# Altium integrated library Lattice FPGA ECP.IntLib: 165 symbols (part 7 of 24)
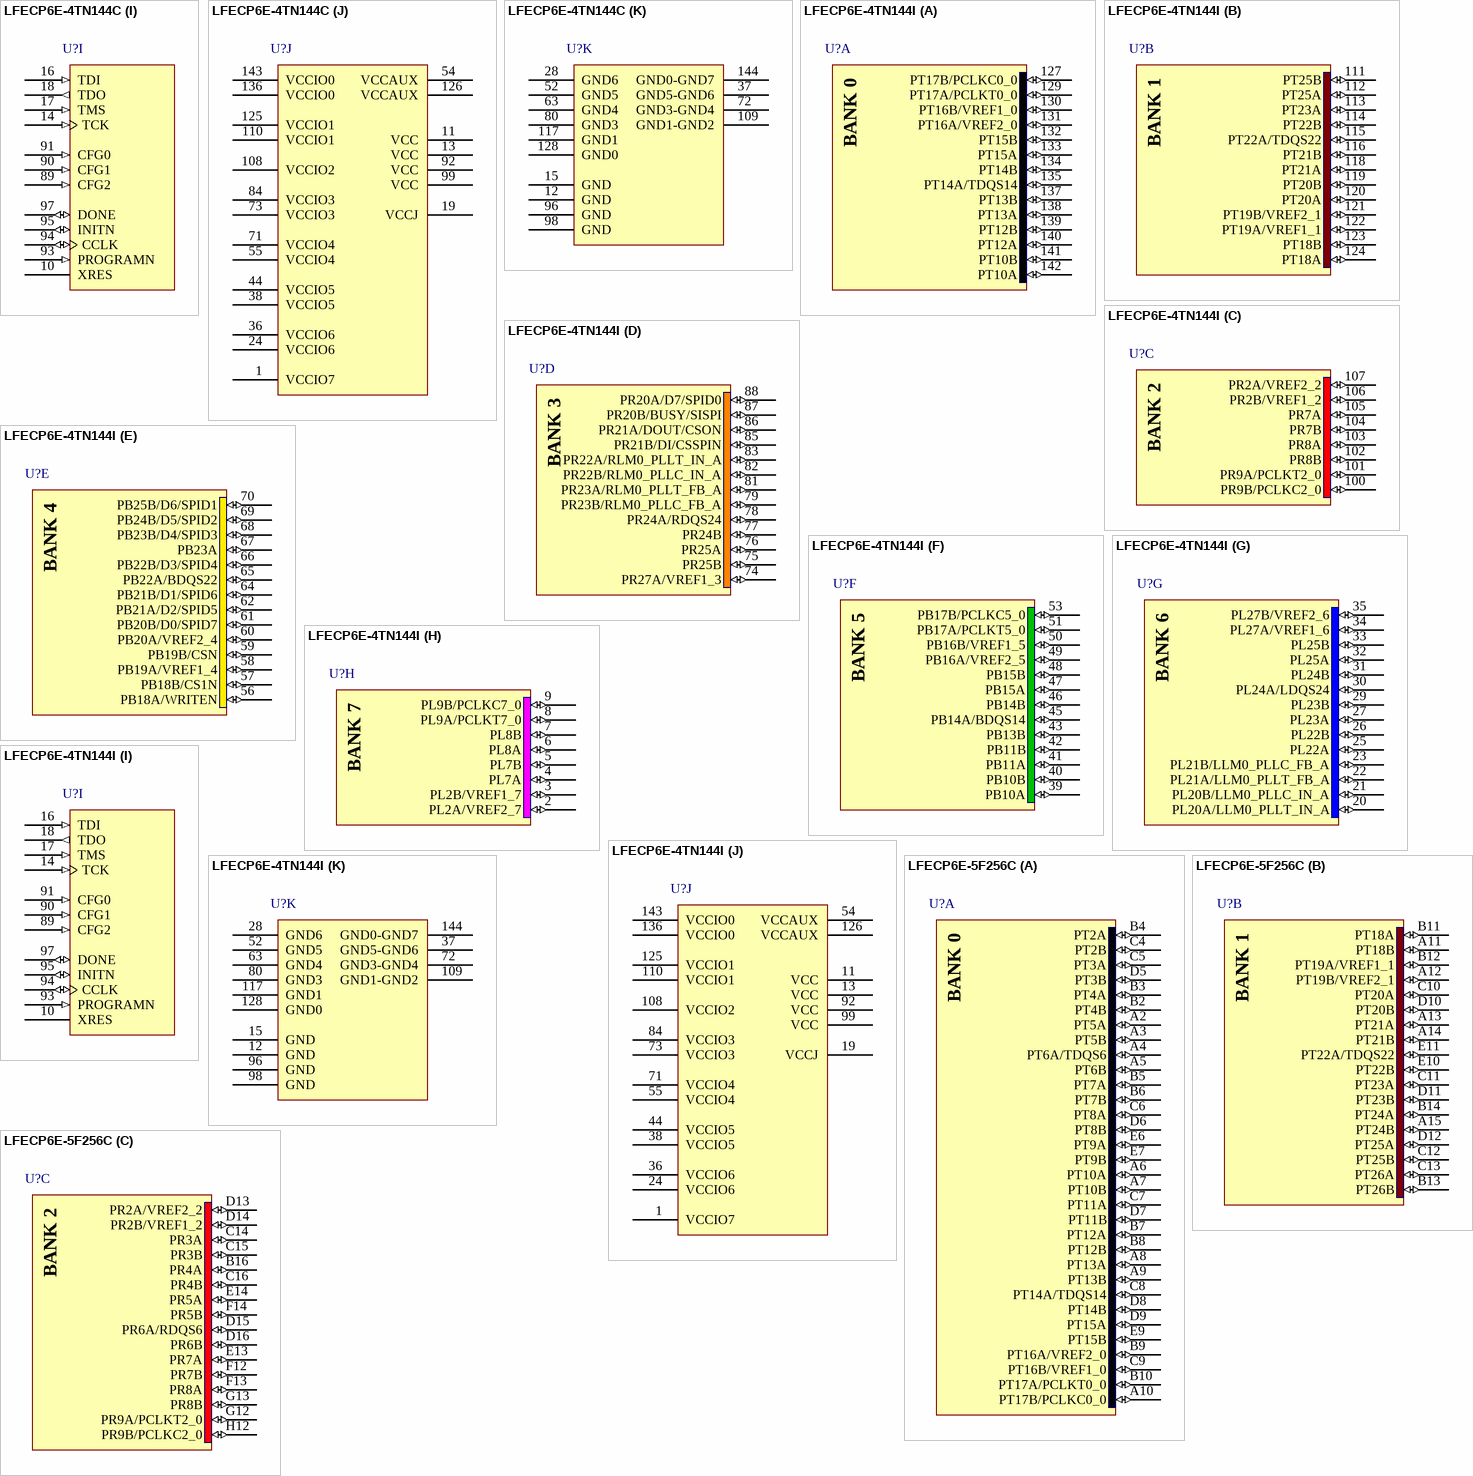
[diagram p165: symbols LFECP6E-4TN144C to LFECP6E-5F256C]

## LFECP6E-4TN144I
designator U?
ECP 1.2V FPGA, 97 I/Os, 2 PLLs, 6.1K LUTs, 4 sysDSP Blocks, 16 18x18 Multipliers, 144-Pin TQFP, Pb-Free, Speed Grade 4, Industrial Temperature Grade; Note: Pins 37, 72, 109 and 144 are double bonded.
footprint TQFP144_N (Thin QFP, 144-Leads, Body 20x20mm, Pitch 0.5mm, IPC Medium Density)
footprint TQFP144_L (Thin QFP, 144-Leads, Body 20x20mm, Pitch 0.5mm, IPC High Density)
footprint TQFP144_M (Thin QFP, 144-Leads, Body 20x20mm, Pitch 0.5mm, IPC Low Density)
3D model ECP6E-TQFP-144 (144-Pin Thin Quad Flat Pack (TQFP144))
part A pins: 127 PT17B/PCLKC0_0 (io), 129 PT17A/PCLKT0_0 (io), 130 PT16B/VREF1_0 (io), 131 PT16A/VREF2_0 (io), 132 PT15B (io), 133 PT15A (io), 134 PT14B (io), 135 PT14A/TDQS14 (io), 137 PT13B (io), 138 PT13A (io), 139 PT12B (io), 140 PT12A (io), 141 PT10B (io), 142 PT10A (io)
part B pins: 111 PT25B (io), 112 PT25A (io), 113 PT23A (io), 114 PT22B (io), 115 PT22A/TDQS22 (io), 116 PT21B (io), 118 PT21A (io), 119 PT20B (io), 120 PT20A (io), 121 PT19B/VREF2_1 (io), 122 PT19A/VREF1_1 (io), 123 PT18B (io), 124 PT18A (io)
part C pins: 100 PR9B/PCLKC2_0 (io), 101 PR9A/PCLKT2_0 (io), 102 PR8B (io), 103 PR8A (io), 104 PR7B (io), 105 PR7A (io), 106 PR2B/VREF1_2 (io), 107 PR2A/VREF2_2 (io)
part D pins: 74 PR27A/VREF1_3 (io), 75 PR25B (io), 76 PR25A (io), 77 PR24B (io), 78 PR24A/RDQS24 (io), 79 PR23B/RLM0_PLLC_FB_A (io), 81 PR23A/RLM0_PLLT_FB_A (io), 82 PR22B/RLM0_PLLC_IN_A (io), 83 PR22A/RLM0_PLLT_IN_A (io), 85 PR21B/DI/CSSPIN (io), 86 PR21A/DOUT/CSON (io), 87 PR20B/BUSY/SISPI (io), 88 PR20A/D7/SPID0 (io)
part E pins: 56 PB18A/WRITEN (io), 57 PB18B/CS1N (io), 58 PB19A/VREF1_4 (io), 59 PB19B/CSN (io), 60 PB20A/VREF2_4 (io), 61 PB20B/D0/SPID7 (io), 62 PB21A/D2/SPID5 (io), 64 PB21B/D1/SPID6 (io), 65 PB22A/BDQS22 (io), 66 PB22B/D3/SPID4 (io), 67 PB23A (io), 68 PB23B/D4/SPID3 (io), 69 PB24B/D5/SPID2 (io), 70 PB25B/D6/SPID1 (io)
part F pins: 39 PB10A (io), 40 PB10B (io), 41 PB11A (io), 42 PB11B (io), 43 PB13B (io), 45 PB14A/BDQS14 (io), 46 PB14B (io), 47 PB15A (io), 48 PB15B (io), 49 PB16A/VREF2_5 (io), 50 PB16B/VREF1_5 (io), 51 PB17A/PCLKT5_0 (io), 53 PB17B/PCLKC5_0 (io)
part G pins: 20 PL20A/LLM0_PLLT_IN_A (io), 21 PL20B/LLM0_PLLC_IN_A (io), 22 PL21A/LLM0_PLLT_FB_A (io), 23 PL21B/LLM0_PLLC_FB_A (io), 25 PL22A (io), 26 PL22B (io), 27 PL23A (io), 29 PL23B (io), 30 PL24A/LDQS24 (io), 31 PL24B (io), 32 PL25A (io), 33 PL25B (io), 34 PL27A/VREF1_6 (io), 35 PL27B/VREF2_6 (io)
part H pins: 2 PL2A/VREF2_7 (io), 3 PL2B/VREF1_7 (io), 4 PL7A (io), 5 PL7B (io), 6 PL8A (io), 7 PL8B (io), 8 PL9A/PCLKT7_0 (io), 9 PL9B/PCLKC7_0 (io)
part I pins: 10 XRES, 14 TCK (in), 16 TDI (in), 17 TMS (in), 18 TDO (out), 89 CFG2 (in), 90 CFG1 (in), 91 CFG0 (in), 93 PROGRAMN (in), 94 CCLK (io), 95 INITN (io), 97 DONE (io)
part J pins: 1 VCCIO7 (power), 11 VCC (power), 13 VCC (power), 19 VCCJ (power), 24 VCCIO6 (power), 36 VCCIO6 (power), 38 VCCIO5 (power), 44 VCCIO5 (power), 54 VCCAUX (power), 55 VCCIO4 (power), 71 VCCIO4 (power), 73 VCCIO3 (power), 84 VCCIO3 (power), 92 VCC (power), 99 VCC (power), 108 VCCIO2 (power), 110 VCCIO1 (power), 125 VCCIO1 (power), 126 VCCAUX (power), 136 VCCIO0 (power), 143 VCCIO0 (power)
part K pins: 12 GND (power), 15 GND (power), 28 GND6 (power), 37 GND5-GND6 (power), 52 GND5 (power), 63 GND4 (power), 72 GND3-GND4 (power), 80 GND3 (power), 96 GND (power), 98 GND (power), 109 GND1-GND2 (power), 117 GND1 (power), 128 GND0 (power), 144 GND0-GND7 (power)

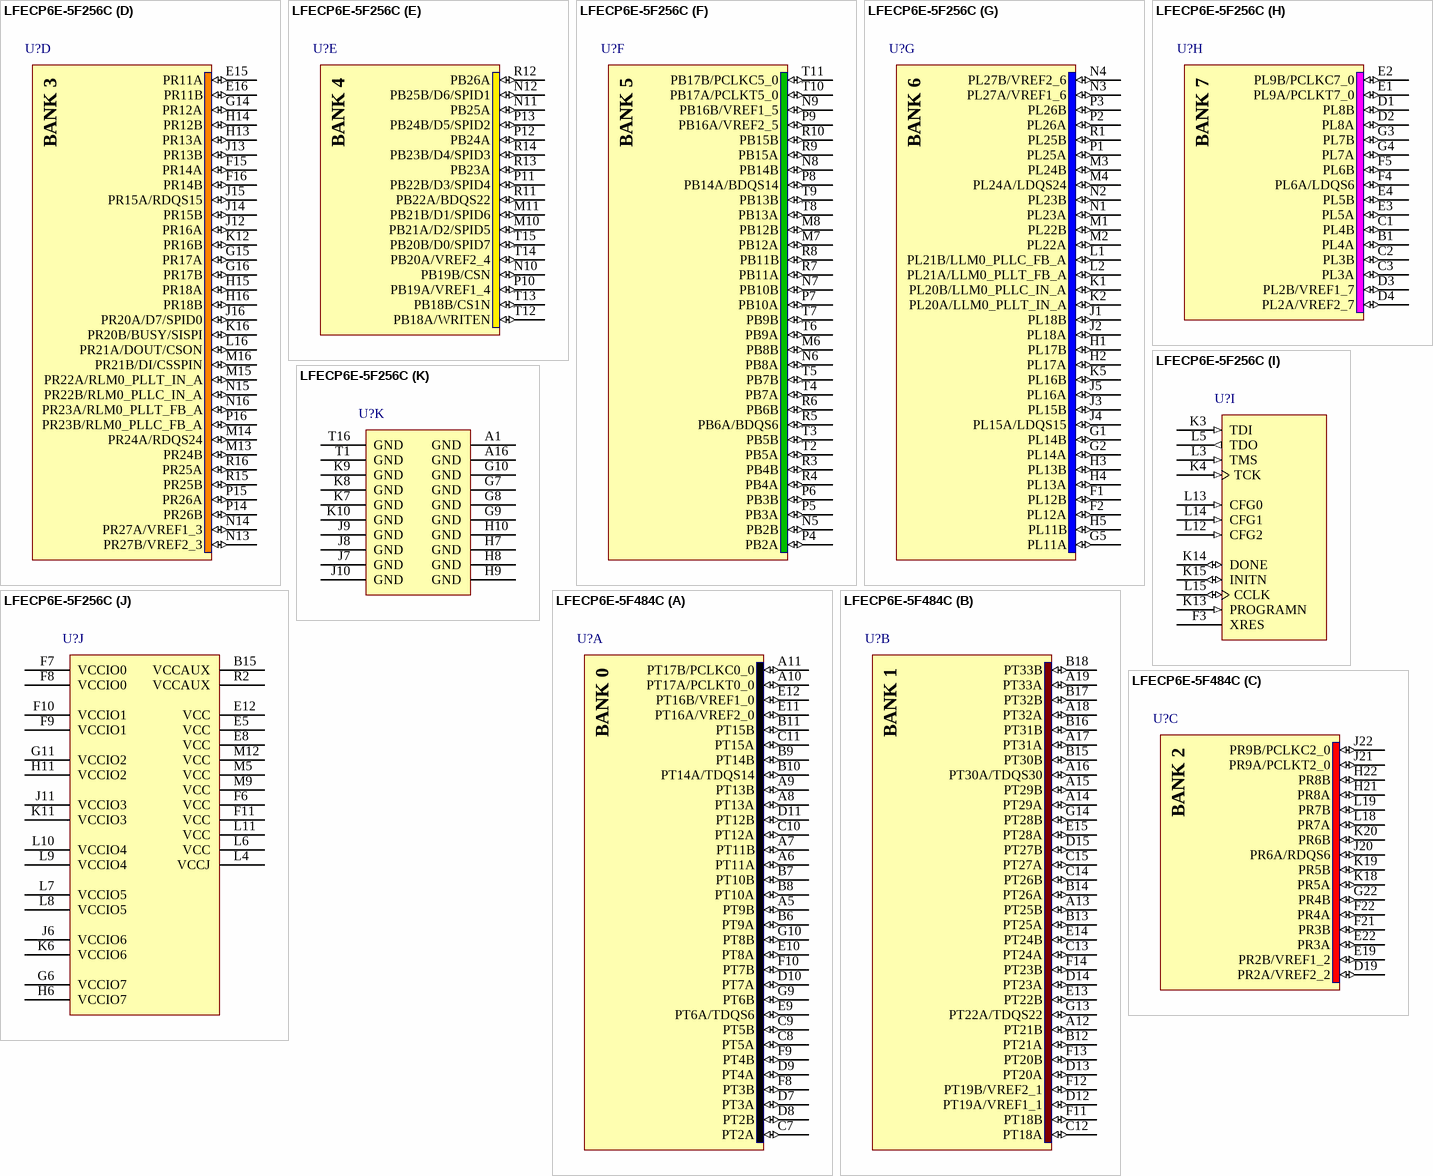
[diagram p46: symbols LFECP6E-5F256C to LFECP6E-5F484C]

## LFECP6E-5F256C
designator U?
ECP 1.2V FPGA, 192 I/Os, 2 PLLs, 6.1K LUTs, 4 sysDSP Blocks, 16 18x18 Multipliers, 256-Pin fpBGA, Speed Grade 5, Commercial Temperature Grade
footprint fpBGA256 (BGA, 256-Leads, Body 17x17mm, Pitch 1mm)
3D model ECP6E-fpBGA256 (256-Ball Fine Pitch Ball Grid Array (fpBGA256))
part A pins: A2 PT5A (io), A3 PT5B (io), A4 PT6A/TDQS6 (io), A5 PT6B (io), A6 PT10A (io), A7 PT10B (io), A8 PT13A (io), A9 PT13B (io), A10 PT17B/PCLKC0_0 (io), B2 PT4B (io), B3 PT4A (io), B4 PT2A (io), B5 PT7A (io), B6 PT7B (io), B7 PT12A (io), B8 PT12B (io), B9 PT16A/VREF2_0 (io), B10 PT17A/PCLKT0_0 (io), C4 PT2B (io), C5 PT3A (io), C6 PT8A (io), C7 PT11A (io), C8 PT14A/TDQS14 (io), C9 PT16B/VREF1_0 (io), D5 PT3B (io), D6 PT8B (io), D7 PT11B (io), D8 PT14B (io), D9 PT15A (io), E6 PT9A (io), E7 PT9B (io), E9 PT15B (io)
part B pins: A11 PT18B (io), A12 PT19B/VREF2_1 (io), A13 PT21A (io), A14 PT21B (io), A15 PT24B (io), B11 PT18A (io), B12 PT19A/VREF1_1 (io), B13 PT26B (io), B14 PT24A (io), C10 PT20A (io), C11 PT23A (io), C12 PT25B (io), C13 PT26A (io), D10 PT20B (io), D11 PT23B (io), D12 PT25A (io), E10 PT22B (io), E11 PT22A/TDQS22 (io)
part C pins: B16 PR4A (io), C14 PR3A (io), C15 PR3B (io), C16 PR4B (io), D13 PR2A/VREF2_2 (io), D14 PR2B/VREF1_2 (io), D15 PR6A/RDQS6 (io), D16 PR6B (io), E13 PR7A (io), E14 PR5A (io), F12 PR7B (io), F13 PR8A (io), F14 PR5B (io), G12 PR9A/PCLKT2_0 (io), G13 PR8B (io), H12 PR9B/PCLKC2_0 (io)
part D pins: E15 PR11A (io), E16 PR11B (io), F15 PR14A (io), F16 PR14B (io), G14 PR12A (io), G15 PR17A (io), G16 PR17B (io), H13 PR13A (io), H14 PR12B (io), H15 PR18A (io), H16 PR18B (io), J12 PR16A (io), J13 PR13B (io), J14 PR15B (io), J15 PR15A/RDQS15 (io), J16 PR20A/D7/SPID0 (io), K12 PR16B (io), K16 PR20B/BUSY/SISPI (io), L16 PR21A/DOUT/CSON (io), M13 PR24B (io), M14 PR24A/RDQS24 (io), M15 PR22A/RLM0_PLLT_IN_A (io), M16 PR21B/DI/CSSPIN (io), N13 PR27B/VREF2_3 (io), N14 PR27A/VREF1_3 (io), N15 PR22B/RLM0_PLLC_IN_A (io), N16 PR23A/RLM0_PLLT_FB_A (io), P14 PR26B (io), P15 PR26A (io), P16 PR23B/RLM0_PLLC_FB_A (io), R15 PR25B (io), R16 PR25A (io)
part E pins: M10 PB21A/D2/SPID5 (io), M11 PB21B/D1/SPID6 (io), N10 PB19B/CSN (io), N11 PB25A (io), N12 PB25B/D6/SPID1 (io), P10 PB19A/VREF1_4 (io), P11 PB22B/D3/SPID4 (io), P12 PB24A (io), P13 PB24B/D5/SPID2 (io), R11 PB22A/BDQS22 (io), R12 PB26A (io), R13 PB23A (io), R14 PB23B/D4/SPID3 (io), T12 PB18A/WRITEN (io), T13 PB18B/CS1N (io), T14 PB20A/VREF2_4 (io), T15 PB20B/D0/SPID7 (io)
part F pins: M6 PB8B (io), M7 PB12A (io), M8 PB12B (io), N5 PB2B (io), N6 PB8A (io), N7 PB10B (io), N8 PB14B (io), N9 PB16B/VREF1_5 (io), P4 PB2A (io), P5 PB3A (io), P6 PB3B (io), P7 PB10A (io), P8 PB14A/BDQS14 (io), P9 PB16A/VREF2_5 (io), R3 PB4B (io), R4 PB4A (io), R5 PB6A/BDQS6 (io), R6 PB6B (io), R7 PB11A (io), R8 PB11B (io), R9 PB15A (io), R10 PB15B (io), T2 PB5A (io), T3 PB5B (io), T4 PB7A (io), T5 PB7B (io), T6 PB9A (io), T7 PB9B (io), T8 PB13A (io), T9 PB13B (io), T10 PB17A/PCLKT5_0 (io), T11 PB17B/PCLKC5_0 (io)
part G pins: F1 PL12B (io), F2 PL12A (io), G1 PL14B (io), G2 PL14A (io), G5 PL11A (io), H1 PL17B (io), H2 PL17A (io), H3 PL13B (io), H4 PL13A (io), H5 PL11B (io), J1 PL18B (io), J2 PL18A (io), J3 PL15B (io), J4 PL15A/LDQS15 (io), J5 PL16A (io), K1 PL20B/LLM0_PLLC_IN_A (io), K2 PL20A/LLM0_PLLT_IN_A (io), K5 PL16B (io), L1 PL21B/LLM0_PLLC_FB_A (io), L2 PL21A/LLM0_PLLT_FB_A (io), M1 PL22B (io), M2 PL22A (io), M3 PL24B (io), M4 PL24A/LDQS24 (io), N1 PL23A (io), N2 PL23B (io), N3 PL27A/VREF1_6 (io), N4 PL27B/VREF2_6 (io), P1 PL25A (io), P2 PL26A (io), P3 PL26B (io), R1 PL25B (io)
part H pins: B1 PL4A (io), C1 PL4B (io), C2 PL3B (io), C3 PL3A (io), D1 PL8B (io), D2 PL8A (io), D3 PL2B/VREF1_7 (io), D4 PL2A/VREF2_7 (io), E1 PL9A/PCLKT7_0 (io), E2 PL9B/PCLKC7_0 (io), E3 PL5A (io), E4 PL5B (io), F4 PL6A/LDQS6 (io), F5 PL6B (io), G3 PL7B (io), G4 PL7A (io)
part I pins: F3 XRES, K3 TDI (in), K4 TCK (in), K13 PROGRAMN (in), K14 DONE (io), K15 INITN (io), L3 TMS (in), L5 TDO (out), L12 CFG2 (in), L13 CFG0 (in), L14 CFG1 (in), L15 CCLK (io)
part J pins: B15 VCCAUX (power), E5 VCC (power), E8 VCC (power), E12 VCC (power), F6 VCC (power), F7 VCCIO0 (power), F8 VCCIO0 (power), F9 VCCIO1 (power), F10 VCCIO1 (power), F11 VCC (power), G6 VCCIO7 (power), G11 VCCIO2 (power), H6 VCCIO7 (power), H11 VCCIO2 (power), J6 VCCIO6 (power), J11 VCCIO3 (power), K6 VCCIO6 (power), K11 VCCIO3 (power), L4 VCCJ (power), L6 VCC (power), L7 VCCIO5 (power), L8 VCCIO5 (power), L9 VCCIO4 (power), L10 VCCIO4 (power), L11 VCC (power), M5 VCC (power), M9 VCC (power), M12 VCC (power), R2 VCCAUX (power)
part K pins: A1 GND (power), A16 GND (power), G7 GND (power), G8 GND (power), G9 GND (power), G10 GND (power), H7 GND (power), H8 GND (power), H9 GND (power), H10 GND (power), J7 GND (power), J8 GND (power), J9 GND (power), J10 GND (power), K7 GND (power), K8 GND (power), K9 GND (power), K10 GND (power), T1 GND (power), T16 GND (power)

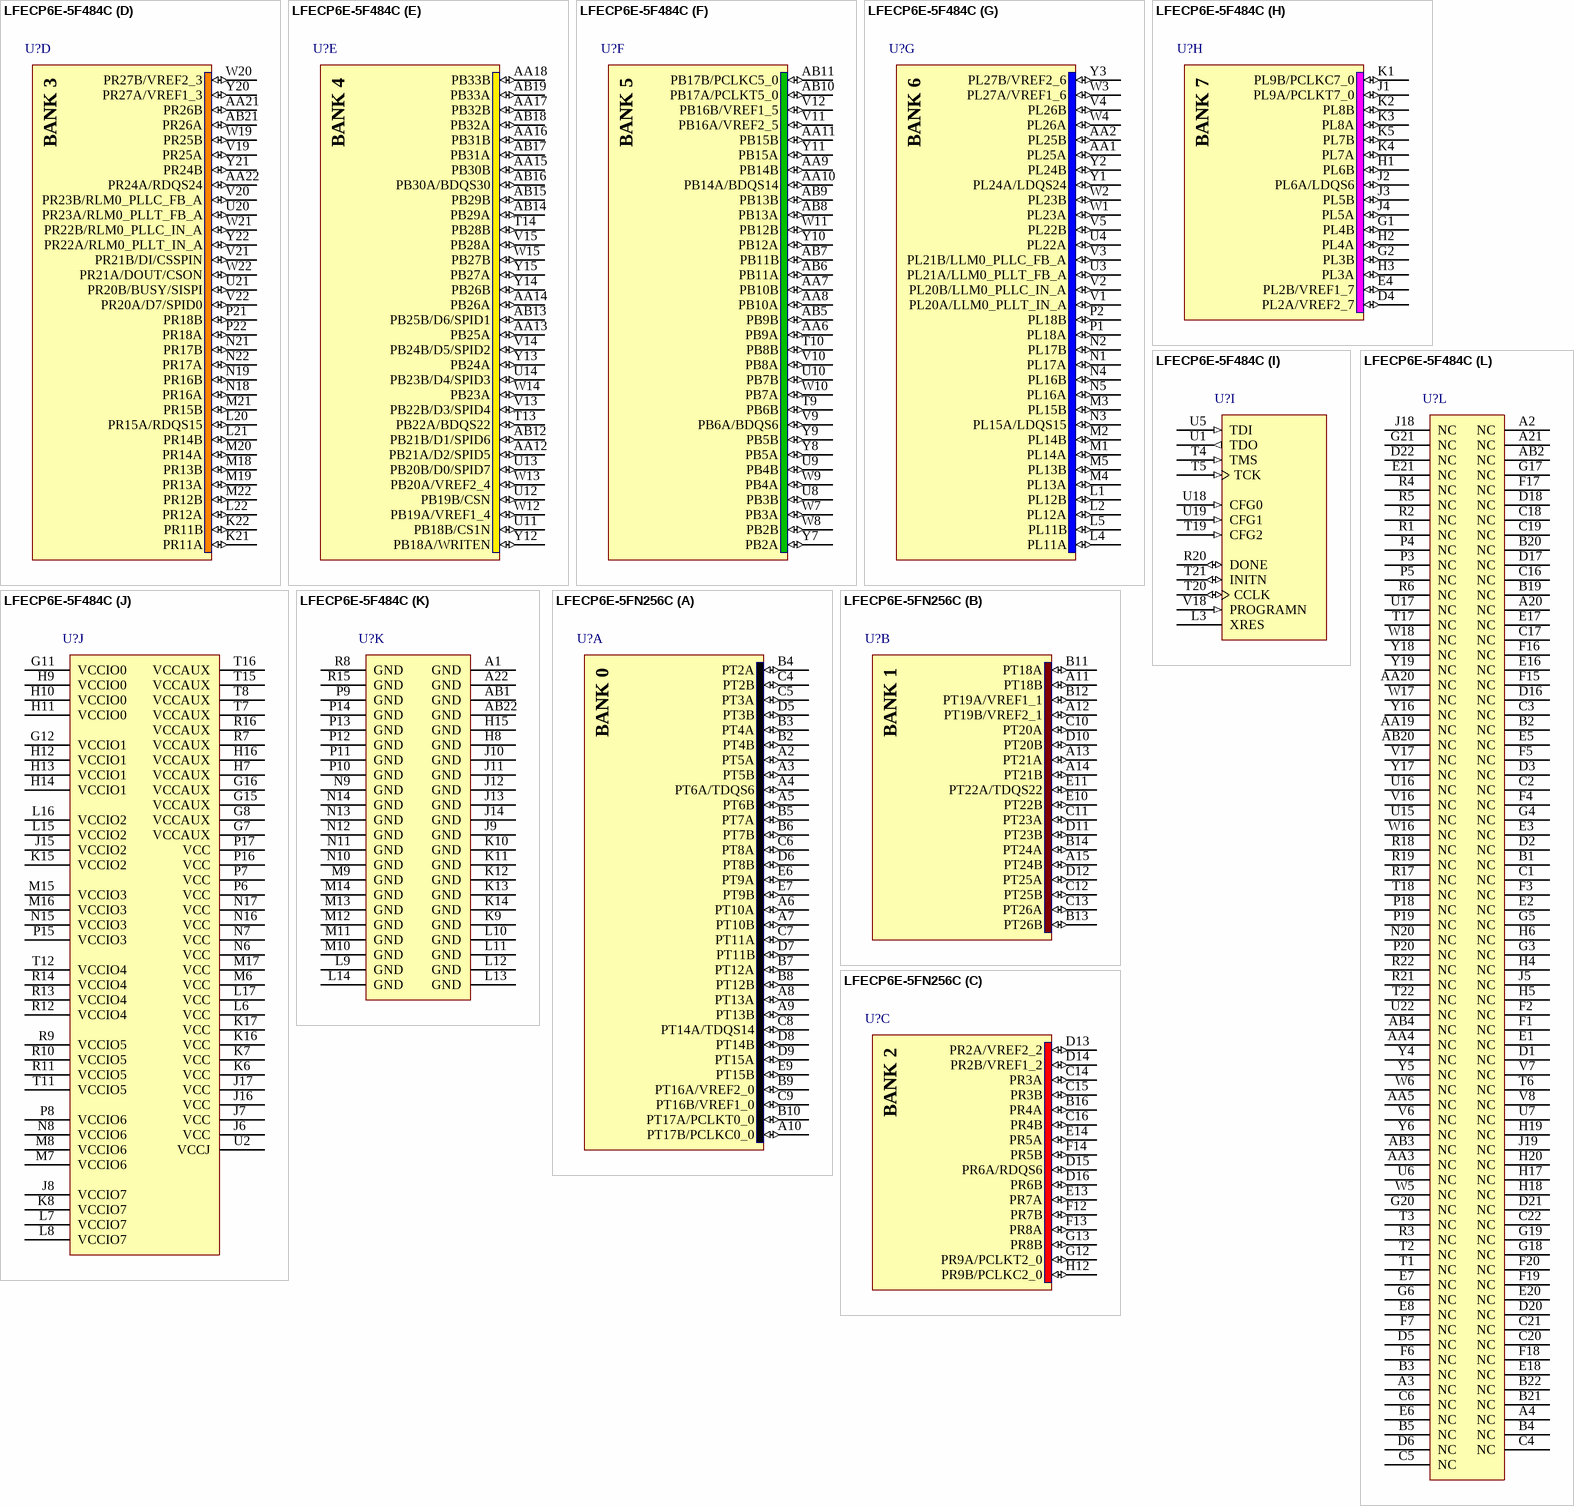
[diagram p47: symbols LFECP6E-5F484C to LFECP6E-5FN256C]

## LFECP6E-5F484C
designator U?
ECP 1.2V FPGA, 224 I/Os, 2 PLLs, 6.1K LUTs, 4 sysDSP Blocks, 16 18x18 Multipliers, 484-Pin fpBGA, Speed Grade 5, Commercial Temperature Grade
footprint fpBGA484 (BGA, 484-Leads, Body 23x23mm, Pitch 1mm)
3D model ECP6E-fpBGA484 (484-Ball Fine Pitch Ball Grid Array (fpBGA484))
part A pins: A5 PT9B (io), A6 PT11A (io), A7 PT11B (io), A8 PT13A (io), A9 PT13B (io), A10 PT17A/PCLKT0_0 (io), A11 PT17B/PCLKC0_0 (io), B6 PT9A (io), B7 PT10B (io), B8 PT10A (io), B9 PT14B (io), B10 PT14A/TDQS14 (io), B11 PT15B (io), C7 PT2A (io), C8 PT5A (io), C9 PT5B (io), C10 PT12A (io), C11 PT15A (io), D7 PT3A (io), D8 PT2B (io), D9 PT4A (io), D10 PT7A (io), D11 PT12B (io), E9 PT6A/TDQS6 (io), E10 PT8A (io), E11 PT16A/VREF2_0 (io), E12 PT16B/VREF1_0 (io), F8 PT3B (io), F9 PT4B (io), F10 PT7B (io), G9 PT6B (io), G10 PT8B (io)
part B pins: A12 PT21B (io), A13 PT25B (io), A14 PT29A (io), A15 PT29B (io), A16 PT30A/TDQS30 (io), A17 PT31A (io), A18 PT32A (io), A19 PT33A (io), B12 PT21A (io), B13 PT25A (io), B14 PT26A (io), B15 PT30B (io), B16 PT31B (io), B17 PT32B (io), B18 PT33B (io), C12 PT18A (io), C13 PT24A (io), C14 PT26B (io), C15 PT27A (io), D12 PT19A/VREF1_1 (io), D13 PT20A (io), D14 PT23A (io), D15 PT27B (io), E13 PT22B (io), E14 PT24B (io), E15 PT28A (io), F11 PT18B (io), F12 PT19B/VREF2_1 (io), F13 PT20B (io), F14 PT23B (io), G13 PT22A/TDQS22 (io), G14 PT28B (io)
part C pins: D19 PR2A/VREF2_2 (io), E19 PR2B/VREF1_2 (io), E22 PR3A (io), F21 PR3B (io), F22 PR4A (io), G22 PR4B (io), H21 PR8A (io), H22 PR8B (io), J20 PR6A/RDQS6 (io), J21 PR9A/PCLKT2_0 (io), J22 PR9B/PCLKC2_0 (io), K18 PR5A (io), K19 PR5B (io), K20 PR6B (io), L18 PR7A (io), L19 PR7B (io)
part D pins: AA21 PR26B (io), AA22 PR24A/RDQS24 (io), AB21 PR26A (io), K21 PR11A (io), K22 PR11B (io), L20 PR15A/RDQS15 (io), L21 PR14B (io), L22 PR12A (io), M18 PR13B (io), M19 PR13A (io), M20 PR14A (io), M21 PR15B (io), M22 PR12B (io), N18 PR16A (io), N19 PR16B (io), N21 PR17B (io), N22 PR17A (io), P21 PR18B (io), P22 PR18A (io), U20 PR23A/RLM0_PLLT_FB_A (io), U21 PR20B/BUSY/SISPI (io), V19 PR25A (io), V20 PR23B/RLM0_PLLC_FB_A (io), V21 PR21B/DI/CSSPIN (io), V22 PR20A/D7/SPID0 (io), W19 PR25B (io), W20 PR27B/VREF2_3 (io), W21 PR22B/RLM0_PLLC_IN_A (io), W22 PR21A/DOUT/CSON (io), Y20 PR27A/VREF1_3 (io), Y21 PR24B (io), Y22 PR22A/RLM0_PLLT_IN_A (io)
part E pins: AA12 PB21A/D2/SPID5 (io), AA13 PB25A (io), AA14 PB26A (io), AA15 PB30B (io), AA16 PB31B (io), AA17 PB32B (io), AA18 PB33B (io), AB12 PB21B/D1/SPID6 (io), AB13 PB25B/D6/SPID1 (io), AB14 PB29A (io), AB15 PB29B (io), AB16 PB30A/BDQS30 (io), AB17 PB31A (io), AB18 PB32A (io), AB19 PB33A (io), T13 PB22A/BDQS22 (io), T14 PB28B (io), U11 PB18B/CS1N (io), U12 PB19B/CSN (io), U13 PB20B/D0/SPID7 (io), U14 PB23B/D4/SPID3 (io), V13 PB22B/D3/SPID4 (io), V14 PB24B/D5/SPID2 (io), V15 PB28A (io), W12 PB19A/VREF1_4 (io), W13 PB20A/VREF2_4 (io), W14 PB23A (io), W15 PB27B (io), Y12 PB18A/WRITEN (io), Y13 PB24A (io), Y14 PB26B (io), Y15 PB27A (io)
part F pins: AA6 PB9A (io), AA7 PB10B (io), AA8 PB10A (io), AA9 PB14B (io), AA10 PB14A/BDQS14 (io), AA11 PB15B (io), AB5 PB9B (io), AB6 PB11A (io), AB7 PB11B (io), AB8 PB13A (io), AB9 PB13B (io), AB10 PB17A/PCLKT5_0 (io), AB11 PB17B/PCLKC5_0 (io), T9 PB6B (io), T10 PB8B (io), U8 PB3B (io), U9 PB4B (io), U10 PB7B (io), V9 PB6A/BDQS6 (io), V10 PB8A (io), V11 PB16A/VREF2_5 (io), V12 PB16B/VREF1_5 (io), W7 PB3A (io), W8 PB2B (io), W9 PB4A (io), W10 PB7A (io), W11 PB12B (io), Y7 PB2A (io), Y8 PB5A (io), Y9 PB5B (io), Y10 PB12A (io), Y11 PB15A (io)
part G pins: AA1 PL25A (io), AA2 PL25B (io), L1 PL12B (io), L2 PL12A (io), L4 PL11A (io), L5 PL11B (io), M1 PL14A (io), M2 PL14B (io), M3 PL15B (io), M4 PL13A (io), M5 PL13B (io), N1 PL17A (io), N2 PL17B (io), N3 PL15A/LDQS15 (io), N4 PL16B (io), N5 PL16A (io), P1 PL18A (io), P2 PL18B (io), U3 PL21A/LLM0_PLLT_FB_A (io), U4 PL22A (io), V1 PL20A/LLM0_PLLT_IN_A (io), V2 PL20B/LLM0_PLLC_IN_A (io), V3 PL21B/LLM0_PLLC_FB_A (io), V4 PL26B (io), V5 PL22B (io), W1 PL23A (io), W2 PL23B (io), W3 PL27A/VREF1_6 (io), W4 PL26A (io), Y1 PL24A/LDQS24 (io), Y2 PL24B (io), Y3 PL27B/VREF2_6 (io)
part H pins: D4 PL2A/VREF2_7 (io), E4 PL2B/VREF1_7 (io), G1 PL4B (io), G2 PL3B (io), H1 PL6B (io), H2 PL4A (io), H3 PL3A (io), J1 PL9A/PCLKT7_0 (io), J2 PL6A/LDQS6 (io), J3 PL5B (io), J4 PL5A (io), K1 PL9B/PCLKC7_0 (io), K2 PL8B (io), K3 PL8A (io), K4 PL7A (io), K5 PL7B (io)
part I pins: L3 XRES, R20 DONE (io), T4 TMS (in), T5 TCK (in), T19 CFG2 (in), T20 CCLK (io), T21 INITN (io), U1 TDO (out), U5 TDI (in), U18 CFG0 (in), U19 CFG1 (in), V18 PROGRAMN (in)
part J pins: G7 VCCAUX (power), G8 VCCAUX (power), G11 VCCIO0 (power), G12 VCCIO1 (power), G15 VCCAUX (power), G16 VCCAUX (power), H7 VCCAUX (power), H9 VCCIO0 (power), H10 VCCIO0 (power), H11 VCCIO0 (power), H12 VCCIO1 (power), H13 VCCIO1 (power), H14 VCCIO1 (power), H16 VCCAUX (power), J6 VCC (power), J7 VCC (power), J8 VCCIO7 (power), J15 VCCIO2 (power), J16 VCC (power), J17 VCC (power), K6 VCC (power), K7 VCC (power), K8 VCCIO7 (power), K15 VCCIO2 (power), K16 VCC (power), K17 VCC (power), L6 VCC (power), L7 VCCIO7 (power), L8 VCCIO7 (power), L15 VCCIO2 (power), L16 VCCIO2 (power), L17 VCC (power), M6 VCC (power), M7 VCCIO6 (power), M8 VCCIO6 (power), M15 VCCIO3 (power), M16 VCCIO3 (power), M17 VCC (power), N6 VCC (power), N7 VCC (power), N8 VCCIO6 (power), N15 VCCIO3 (power), N16 VCC (power), N17 VCC (power), P6 VCC (power), P7 VCC (power), P8 VCCIO6 (power), P15 VCCIO3 (power), P16 VCC (power), P17 VCC (power), R7 VCCAUX (power), R9 VCCIO5 (power), R10 VCCIO5 (power), R11 VCCIO5 (power), R12 VCCIO4 (power), R13 VCCIO4 (power), R14 VCCIO4 (power), R16 VCCAUX (power), T7 VCCAUX (power), T8 VCCAUX (power), T11 VCCIO5 (power), T12 VCCIO4 (power), T15 VCCAUX (power), T16 VCCAUX (power), U2 VCCJ (power)
part K pins: A1 GND (power), A22 GND (power), AB1 GND (power), AB22 GND (power), H8 GND (power), H15 GND (power), J9 GND (power), J10 GND (power), J11 GND (power), J12 GND (power), J13 GND (power), J14 GND (power), K9 GND (power), K10 GND (power), K11 GND (power), K12 GND (power), K13 GND (power), K14 GND (power), L9 GND (power), L10 GND (power), L11 GND (power), L12 GND (power), L13 GND (power), L14 GND (power), M9 GND (power), M10 GND (power), M11 GND (power), M12 GND (power), M13 GND (power), M14 GND (power), N9 GND (power), N10 GND (power), N11 GND (power), N12 GND (power), N13 GND (power), N14 GND (power), P9 GND (power), P10 GND (power), P11 GND (power), P12 GND (power), P13 GND (power), P14 GND (power), R8 GND (power), R15 GND (power)
part L pins: A2 NC, A3 NC, A4 NC, A20 NC, A21 NC, AA3 NC, AA4 NC, AA5 NC, AA19 NC, AA20 NC, AB2 NC, AB3 NC, AB4 NC, AB20 NC, B1 NC, B2 NC, B3 NC, B4 NC, B5 NC, B19 NC, B20 NC, B21 NC, B22 NC, C1 NC, C2 NC, C3 NC, C4 NC, C5 NC, C6 NC, C16 NC, C17 NC, C18 NC, C19 NC, C20 NC, C21 NC, C22 NC, D1 NC, D2 NC, D3 NC, D5 NC, D6 NC, D16 NC, D17 NC, D18 NC, D20 NC, D21 NC, D22 NC, E1 NC, E2 NC, E3 NC, E5 NC, E6 NC, E7 NC, E8 NC, E16 NC, E17 NC, E18 NC, E20 NC, E21 NC, F1 NC, F2 NC, F3 NC, F4 NC, F5 NC, F6 NC, F7 NC, F15 NC, F16 NC, F17 NC, F18 NC, F19 NC, F20 NC, G3 NC, G4 NC, G5 NC, G6 NC, G17 NC, G18 NC, G19 NC, G20 NC, G21 NC, H4 NC, H5 NC, H6 NC, H17 NC, H18 NC, H19 NC, H20 NC, J5 NC, J18 NC, J19 NC, N20 NC, P3 NC, P4 NC, P5 NC, P18 NC, P19 NC, P20 NC, R1 NC, R2 NC, R3 NC, R4 NC, R5 NC, R6 NC, R17 NC, R18 NC, R19 NC, R21 NC, R22 NC, T1 NC, T2 NC, T3 NC, T6 NC, T17 NC, T18 NC, T22 NC, U6 NC, U7 NC, U15 NC, U16 NC, U17 NC, U22 NC, V6 NC, V7 NC, V8 NC, V16 NC, V17 NC, W5 NC, W6 NC, W16 NC, W17 NC, W18 NC, Y4 NC, Y5 NC, Y6 NC, Y16 NC, Y17 NC, Y18 NC, Y19 NC

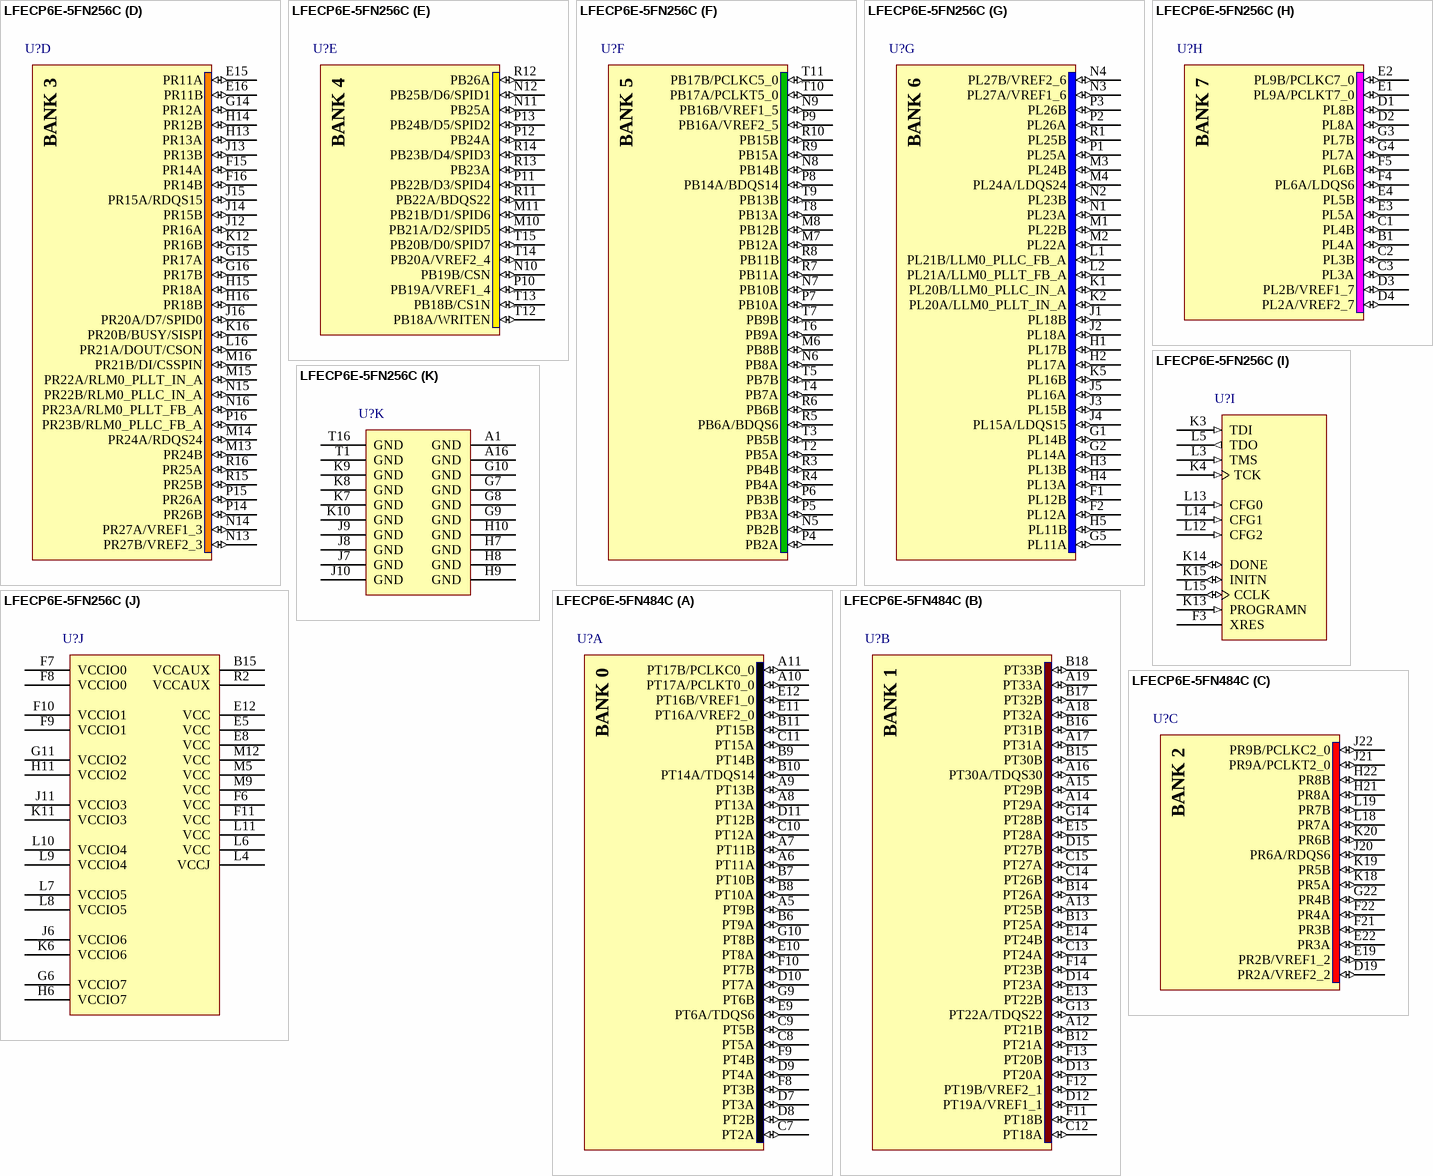
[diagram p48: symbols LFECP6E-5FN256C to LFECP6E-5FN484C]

## LFECP6E-5FN256C
designator U?
ECP 1.2V FPGA, 195 I/Os, 2 PLLs, 6.1K LUTs, 4 sysDSP Blocks, 16 18x18 Multipliers, 256-Pin fpBGA, Pb-Free, Speed Grade 5, Commercial Temperature Grade
footprint fpBGA256 (BGA, 256-Leads, Body 17x17mm, Pitch 1mm)
3D model ECP6E-fpBGA256 (256-Ball Fine Pitch Ball Grid Array (fpBGA256))
part A pins: A2 PT5A (io), A3 PT5B (io), A4 PT6A/TDQS6 (io), A5 PT6B (io), A6 PT10A (io), A7 PT10B (io), A8 PT13A (io), A9 PT13B (io), A10 PT17B/PCLKC0_0 (io), B2 PT4B (io), B3 PT4A (io), B4 PT2A (io), B5 PT7A (io), B6 PT7B (io), B7 PT12A (io), B8 PT12B (io), B9 PT16A/VREF2_0 (io), B10 PT17A/PCLKT0_0 (io), C4 PT2B (io), C5 PT3A (io), C6 PT8A (io), C7 PT11A (io), C8 PT14A/TDQS14 (io), C9 PT16B/VREF1_0 (io), D5 PT3B (io), D6 PT8B (io), D7 PT11B (io), D8 PT14B (io), D9 PT15A (io), E6 PT9A (io), E7 PT9B (io), E9 PT15B (io)
part B pins: A11 PT18B (io), A12 PT19B/VREF2_1 (io), A13 PT21A (io), A14 PT21B (io), A15 PT24B (io), B11 PT18A (io), B12 PT19A/VREF1_1 (io), B13 PT26B (io), B14 PT24A (io), C10 PT20A (io), C11 PT23A (io), C12 PT25B (io), C13 PT26A (io), D10 PT20B (io), D11 PT23B (io), D12 PT25A (io), E10 PT22B (io), E11 PT22A/TDQS22 (io)
part C pins: B16 PR4A (io), C14 PR3A (io), C15 PR3B (io), C16 PR4B (io), D13 PR2A/VREF2_2 (io), D14 PR2B/VREF1_2 (io), D15 PR6A/RDQS6 (io), D16 PR6B (io), E13 PR7A (io), E14 PR5A (io), F12 PR7B (io), F13 PR8A (io), F14 PR5B (io), G12 PR9A/PCLKT2_0 (io), G13 PR8B (io), H12 PR9B/PCLKC2_0 (io)
part D pins: E15 PR11A (io), E16 PR11B (io), F15 PR14A (io), F16 PR14B (io), G14 PR12A (io), G15 PR17A (io), G16 PR17B (io), H13 PR13A (io), H14 PR12B (io), H15 PR18A (io), H16 PR18B (io), J12 PR16A (io), J13 PR13B (io), J14 PR15B (io), J15 PR15A/RDQS15 (io), J16 PR20A/D7/SPID0 (io), K12 PR16B (io), K16 PR20B/BUSY/SISPI (io), L16 PR21A/DOUT/CSON (io), M13 PR24B (io), M14 PR24A/RDQS24 (io), M15 PR22A/RLM0_PLLT_IN_A (io), M16 PR21B/DI/CSSPIN (io), N13 PR27B/VREF2_3 (io), N14 PR27A/VREF1_3 (io), N15 PR22B/RLM0_PLLC_IN_A (io), N16 PR23A/RLM0_PLLT_FB_A (io), P14 PR26B (io), P15 PR26A (io), P16 PR23B/RLM0_PLLC_FB_A (io), R15 PR25B (io), R16 PR25A (io)
part E pins: M10 PB21A/D2/SPID5 (io), M11 PB21B/D1/SPID6 (io), N10 PB19B/CSN (io), N11 PB25A (io), N12 PB25B/D6/SPID1 (io), P10 PB19A/VREF1_4 (io), P11 PB22B/D3/SPID4 (io), P12 PB24A (io), P13 PB24B/D5/SPID2 (io), R11 PB22A/BDQS22 (io), R12 PB26A (io), R13 PB23A (io), R14 PB23B/D4/SPID3 (io), T12 PB18A/WRITEN (io), T13 PB18B/CS1N (io), T14 PB20A/VREF2_4 (io), T15 PB20B/D0/SPID7 (io)
part F pins: M6 PB8B (io), M7 PB12A (io), M8 PB12B (io), N5 PB2B (io), N6 PB8A (io), N7 PB10B (io), N8 PB14B (io), N9 PB16B/VREF1_5 (io), P4 PB2A (io), P5 PB3A (io), P6 PB3B (io), P7 PB10A (io), P8 PB14A/BDQS14 (io), P9 PB16A/VREF2_5 (io), R3 PB4B (io), R4 PB4A (io), R5 PB6A/BDQS6 (io), R6 PB6B (io), R7 PB11A (io), R8 PB11B (io), R9 PB15A (io), R10 PB15B (io), T2 PB5A (io), T3 PB5B (io), T4 PB7A (io), T5 PB7B (io), T6 PB9A (io), T7 PB9B (io), T8 PB13A (io), T9 PB13B (io), T10 PB17A/PCLKT5_0 (io), T11 PB17B/PCLKC5_0 (io)
part G pins: F1 PL12B (io), F2 PL12A (io), G1 PL14B (io), G2 PL14A (io), G5 PL11A (io), H1 PL17B (io), H2 PL17A (io), H3 PL13B (io), H4 PL13A (io), H5 PL11B (io), J1 PL18B (io), J2 PL18A (io), J3 PL15B (io), J4 PL15A/LDQS15 (io), J5 PL16A (io), K1 PL20B/LLM0_PLLC_IN_A (io), K2 PL20A/LLM0_PLLT_IN_A (io), K5 PL16B (io), L1 PL21B/LLM0_PLLC_FB_A (io), L2 PL21A/LLM0_PLLT_FB_A (io), M1 PL22B (io), M2 PL22A (io), M3 PL24B (io), M4 PL24A/LDQS24 (io), N1 PL23A (io), N2 PL23B (io), N3 PL27A/VREF1_6 (io), N4 PL27B/VREF2_6 (io), P1 PL25A (io), P2 PL26A (io), P3 PL26B (io), R1 PL25B (io)
part H pins: B1 PL4A (io), C1 PL4B (io), C2 PL3B (io), C3 PL3A (io), D1 PL8B (io), D2 PL8A (io), D3 PL2B/VREF1_7 (io), D4 PL2A/VREF2_7 (io), E1 PL9A/PCLKT7_0 (io), E2 PL9B/PCLKC7_0 (io), E3 PL5A (io), E4 PL5B (io), F4 PL6A/LDQS6 (io), F5 PL6B (io), G3 PL7B (io), G4 PL7A (io)
part I pins: F3 XRES, K3 TDI (in), K4 TCK (in), K13 PROGRAMN (in), K14 DONE (io), K15 INITN (io), L3 TMS (in), L5 TDO (out), L12 CFG2 (in), L13 CFG0 (in), L14 CFG1 (in), L15 CCLK (io)
part J pins: B15 VCCAUX (power), E5 VCC (power), E8 VCC (power), E12 VCC (power), F6 VCC (power), F7 VCCIO0 (power), F8 VCCIO0 (power), F9 VCCIO1 (power), F10 VCCIO1 (power), F11 VCC (power), G6 VCCIO7 (power), G11 VCCIO2 (power), H6 VCCIO7 (power), H11 VCCIO2 (power), J6 VCCIO6 (power), J11 VCCIO3 (power), K6 VCCIO6 (power), K11 VCCIO3 (power), L4 VCCJ (power), L6 VCC (power), L7 VCCIO5 (power), L8 VCCIO5 (power), L9 VCCIO4 (power), L10 VCCIO4 (power), L11 VCC (power), M5 VCC (power), M9 VCC (power), M12 VCC (power), R2 VCCAUX (power)
part K pins: A1 GND (power), A16 GND (power), G7 GND (power), G8 GND (power), G9 GND (power), G10 GND (power), H7 GND (power), H8 GND (power), H9 GND (power), H10 GND (power), J7 GND (power), J8 GND (power), J9 GND (power), J10 GND (power), K7 GND (power), K8 GND (power), K9 GND (power), K10 GND (power), T1 GND (power), T16 GND (power)

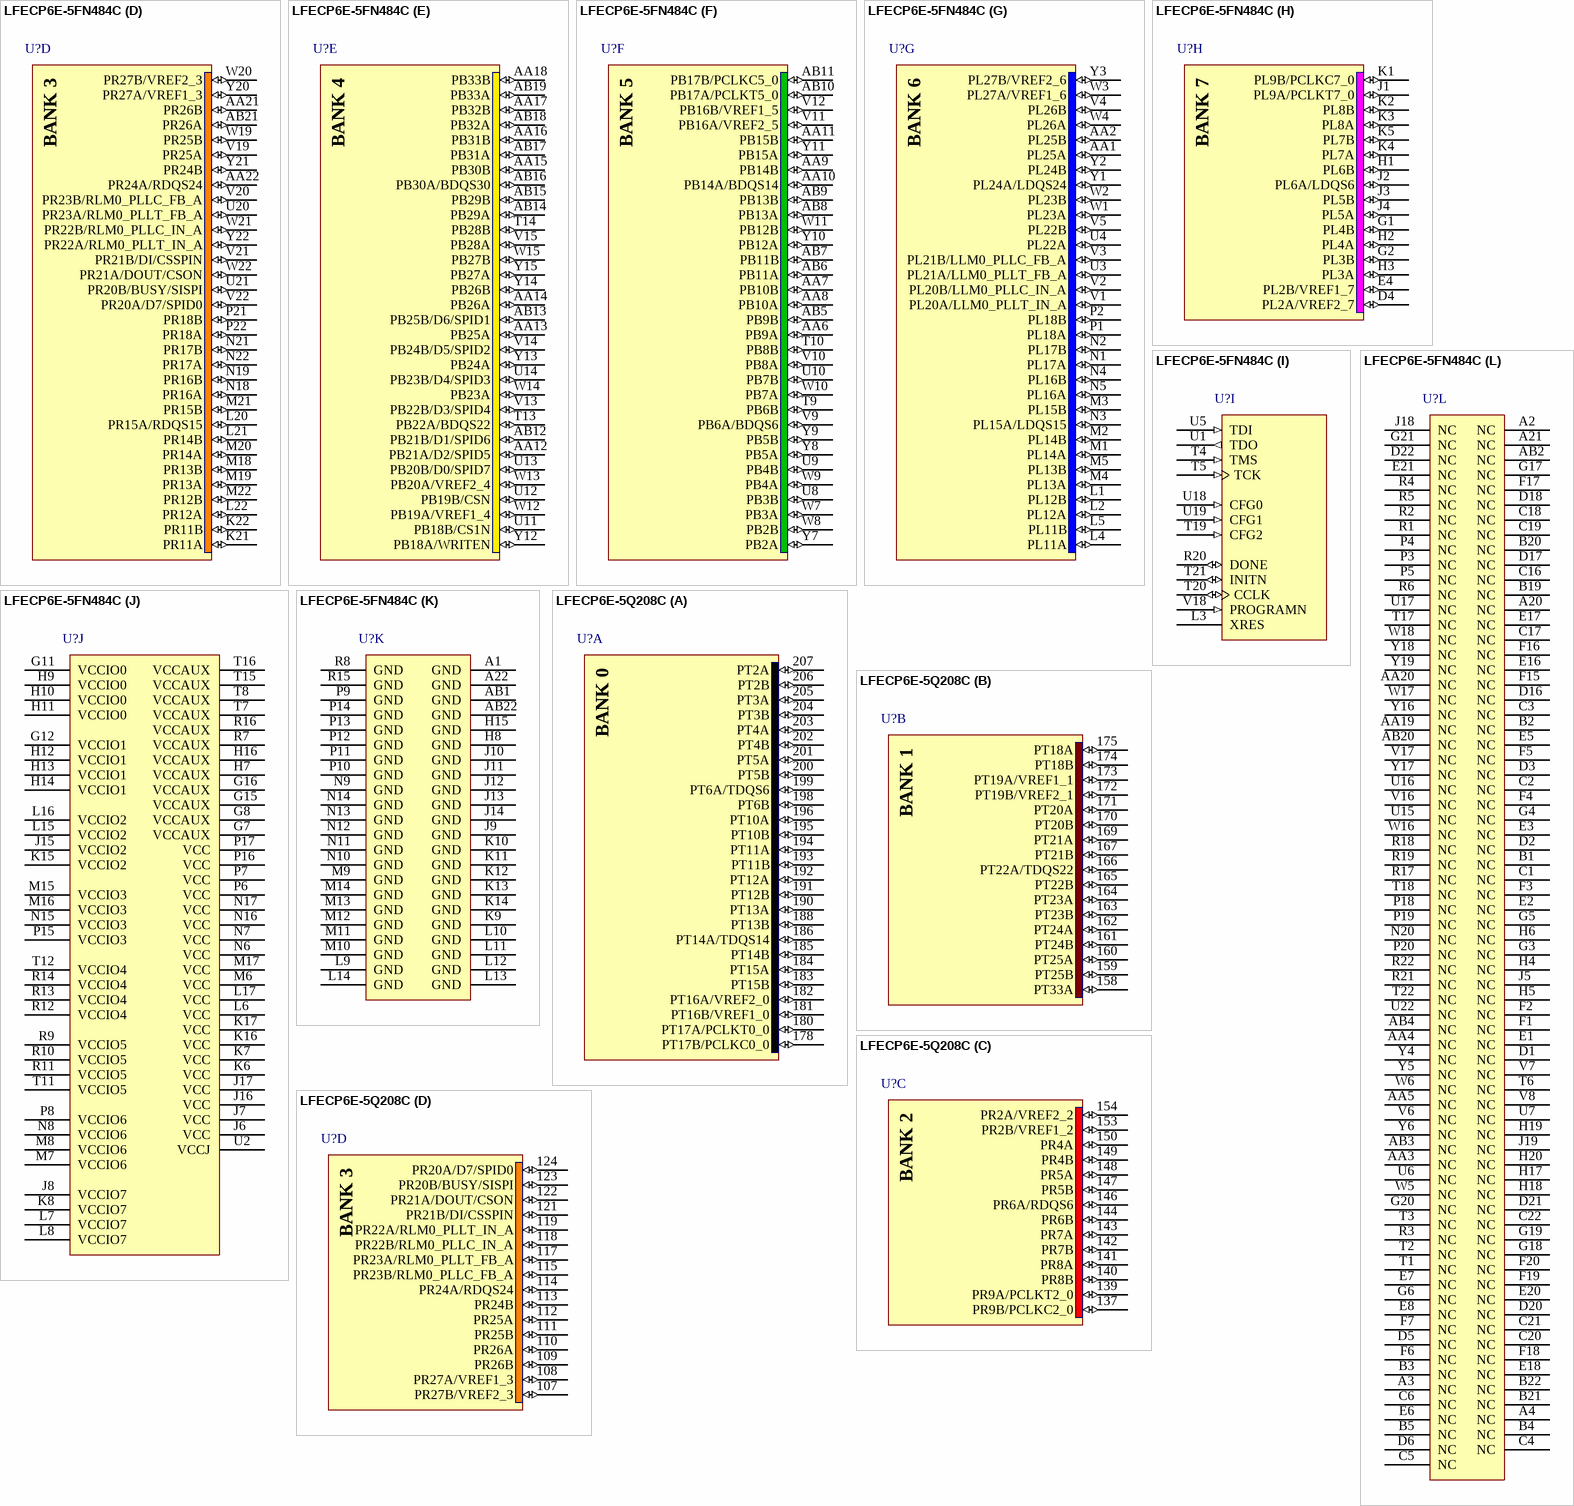
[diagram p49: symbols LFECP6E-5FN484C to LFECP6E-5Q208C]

## LFECP6E-5FN484C
designator U?
ECP 1.2V FPGA, 224 I/Os, 2 PLLs, 6.1K LUTs, 4 sysDSP Blocks, 16 18x18 Multipliers, 484-Pin fpBGA, Pb-Free, Speed Grade 5, Commercial Temperature Grade
footprint fpBGA484 (BGA, 484-Leads, Body 23x23mm, Pitch 1mm)
3D model ECP6E-fpBGA484 (484-Ball Fine Pitch Ball Grid Array (fpBGA484))
part A pins: A5 PT9B (io), A6 PT11A (io), A7 PT11B (io), A8 PT13A (io), A9 PT13B (io), A10 PT17A/PCLKT0_0 (io), A11 PT17B/PCLKC0_0 (io), B6 PT9A (io), B7 PT10B (io), B8 PT10A (io), B9 PT14B (io), B10 PT14A/TDQS14 (io), B11 PT15B (io), C7 PT2A (io), C8 PT5A (io), C9 PT5B (io), C10 PT12A (io), C11 PT15A (io), D7 PT3A (io), D8 PT2B (io), D9 PT4A (io), D10 PT7A (io), D11 PT12B (io), E9 PT6A/TDQS6 (io), E10 PT8A (io), E11 PT16A/VREF2_0 (io), E12 PT16B/VREF1_0 (io), F8 PT3B (io), F9 PT4B (io), F10 PT7B (io), G9 PT6B (io), G10 PT8B (io)
part B pins: A12 PT21B (io), A13 PT25B (io), A14 PT29A (io), A15 PT29B (io), A16 PT30A/TDQS30 (io), A17 PT31A (io), A18 PT32A (io), A19 PT33A (io), B12 PT21A (io), B13 PT25A (io), B14 PT26A (io), B15 PT30B (io), B16 PT31B (io), B17 PT32B (io), B18 PT33B (io), C12 PT18A (io), C13 PT24A (io), C14 PT26B (io), C15 PT27A (io), D12 PT19A/VREF1_1 (io), D13 PT20A (io), D14 PT23A (io), D15 PT27B (io), E13 PT22B (io), E14 PT24B (io), E15 PT28A (io), F11 PT18B (io), F12 PT19B/VREF2_1 (io), F13 PT20B (io), F14 PT23B (io), G13 PT22A/TDQS22 (io), G14 PT28B (io)
part C pins: D19 PR2A/VREF2_2 (io), E19 PR2B/VREF1_2 (io), E22 PR3A (io), F21 PR3B (io), F22 PR4A (io), G22 PR4B (io), H21 PR8A (io), H22 PR8B (io), J20 PR6A/RDQS6 (io), J21 PR9A/PCLKT2_0 (io), J22 PR9B/PCLKC2_0 (io), K18 PR5A (io), K19 PR5B (io), K20 PR6B (io), L18 PR7A (io), L19 PR7B (io)
part D pins: AA21 PR26B (io), AA22 PR24A/RDQS24 (io), AB21 PR26A (io), K21 PR11A (io), K22 PR11B (io), L20 PR15A/RDQS15 (io), L21 PR14B (io), L22 PR12A (io), M18 PR13B (io), M19 PR13A (io), M20 PR14A (io), M21 PR15B (io), M22 PR12B (io), N18 PR16A (io), N19 PR16B (io), N21 PR17B (io), N22 PR17A (io), P21 PR18B (io), P22 PR18A (io), U20 PR23A/RLM0_PLLT_FB_A (io), U21 PR20B/BUSY/SISPI (io), V19 PR25A (io), V20 PR23B/RLM0_PLLC_FB_A (io), V21 PR21B/DI/CSSPIN (io), V22 PR20A/D7/SPID0 (io), W19 PR25B (io), W20 PR27B/VREF2_3 (io), W21 PR22B/RLM0_PLLC_IN_A (io), W22 PR21A/DOUT/CSON (io), Y20 PR27A/VREF1_3 (io), Y21 PR24B (io), Y22 PR22A/RLM0_PLLT_IN_A (io)
part E pins: AA12 PB21A/D2/SPID5 (io), AA13 PB25A (io), AA14 PB26A (io), AA15 PB30B (io), AA16 PB31B (io), AA17 PB32B (io), AA18 PB33B (io), AB12 PB21B/D1/SPID6 (io), AB13 PB25B/D6/SPID1 (io), AB14 PB29A (io), AB15 PB29B (io), AB16 PB30A/BDQS30 (io), AB17 PB31A (io), AB18 PB32A (io), AB19 PB33A (io), T13 PB22A/BDQS22 (io), T14 PB28B (io), U11 PB18B/CS1N (io), U12 PB19B/CSN (io), U13 PB20B/D0/SPID7 (io), U14 PB23B/D4/SPID3 (io), V13 PB22B/D3/SPID4 (io), V14 PB24B/D5/SPID2 (io), V15 PB28A (io), W12 PB19A/VREF1_4 (io), W13 PB20A/VREF2_4 (io), W14 PB23A (io), W15 PB27B (io), Y12 PB18A/WRITEN (io), Y13 PB24A (io), Y14 PB26B (io), Y15 PB27A (io)
part F pins: AA6 PB9A (io), AA7 PB10B (io), AA8 PB10A (io), AA9 PB14B (io), AA10 PB14A/BDQS14 (io), AA11 PB15B (io), AB5 PB9B (io), AB6 PB11A (io), AB7 PB11B (io), AB8 PB13A (io), AB9 PB13B (io), AB10 PB17A/PCLKT5_0 (io), AB11 PB17B/PCLKC5_0 (io), T9 PB6B (io), T10 PB8B (io), U8 PB3B (io), U9 PB4B (io), U10 PB7B (io), V9 PB6A/BDQS6 (io), V10 PB8A (io), V11 PB16A/VREF2_5 (io), V12 PB16B/VREF1_5 (io), W7 PB3A (io), W8 PB2B (io), W9 PB4A (io), W10 PB7A (io), W11 PB12B (io), Y7 PB2A (io), Y8 PB5A (io), Y9 PB5B (io), Y10 PB12A (io), Y11 PB15A (io)
part G pins: AA1 PL25A (io), AA2 PL25B (io), L1 PL12B (io), L2 PL12A (io), L4 PL11A (io), L5 PL11B (io), M1 PL14A (io), M2 PL14B (io), M3 PL15B (io), M4 PL13A (io), M5 PL13B (io), N1 PL17A (io), N2 PL17B (io), N3 PL15A/LDQS15 (io), N4 PL16B (io), N5 PL16A (io), P1 PL18A (io), P2 PL18B (io), U3 PL21A/LLM0_PLLT_FB_A (io), U4 PL22A (io), V1 PL20A/LLM0_PLLT_IN_A (io), V2 PL20B/LLM0_PLLC_IN_A (io), V3 PL21B/LLM0_PLLC_FB_A (io), V4 PL26B (io), V5 PL22B (io), W1 PL23A (io), W2 PL23B (io), W3 PL27A/VREF1_6 (io), W4 PL26A (io), Y1 PL24A/LDQS24 (io), Y2 PL24B (io), Y3 PL27B/VREF2_6 (io)
part H pins: D4 PL2A/VREF2_7 (io), E4 PL2B/VREF1_7 (io), G1 PL4B (io), G2 PL3B (io), H1 PL6B (io), H2 PL4A (io), H3 PL3A (io), J1 PL9A/PCLKT7_0 (io), J2 PL6A/LDQS6 (io), J3 PL5B (io), J4 PL5A (io), K1 PL9B/PCLKC7_0 (io), K2 PL8B (io), K3 PL8A (io), K4 PL7A (io), K5 PL7B (io)
part I pins: L3 XRES, R20 DONE (io), T4 TMS (in), T5 TCK (in), T19 CFG2 (in), T20 CCLK (io), T21 INITN (io), U1 TDO (out), U5 TDI (in), U18 CFG0 (in), U19 CFG1 (in), V18 PROGRAMN (in)
part J pins: G7 VCCAUX (power), G8 VCCAUX (power), G11 VCCIO0 (power), G12 VCCIO1 (power), G15 VCCAUX (power), G16 VCCAUX (power), H7 VCCAUX (power), H9 VCCIO0 (power), H10 VCCIO0 (power), H11 VCCIO0 (power), H12 VCCIO1 (power), H13 VCCIO1 (power), H14 VCCIO1 (power), H16 VCCAUX (power), J6 VCC (power), J7 VCC (power), J8 VCCIO7 (power), J15 VCCIO2 (power), J16 VCC (power), J17 VCC (power), K6 VCC (power), K7 VCC (power), K8 VCCIO7 (power), K15 VCCIO2 (power), K16 VCC (power), K17 VCC (power), L6 VCC (power), L7 VCCIO7 (power), L8 VCCIO7 (power), L15 VCCIO2 (power), L16 VCCIO2 (power), L17 VCC (power), M6 VCC (power), M7 VCCIO6 (power), M8 VCCIO6 (power), M15 VCCIO3 (power), M16 VCCIO3 (power), M17 VCC (power), N6 VCC (power), N7 VCC (power), N8 VCCIO6 (power), N15 VCCIO3 (power), N16 VCC (power), N17 VCC (power), P6 VCC (power), P7 VCC (power), P8 VCCIO6 (power), P15 VCCIO3 (power), P16 VCC (power), P17 VCC (power), R7 VCCAUX (power), R9 VCCIO5 (power), R10 VCCIO5 (power), R11 VCCIO5 (power), R12 VCCIO4 (power), R13 VCCIO4 (power), R14 VCCIO4 (power), R16 VCCAUX (power), T7 VCCAUX (power), T8 VCCAUX (power), T11 VCCIO5 (power), T12 VCCIO4 (power), T15 VCCAUX (power), T16 VCCAUX (power), U2 VCCJ (power)
part K pins: A1 GND (power), A22 GND (power), AB1 GND (power), AB22 GND (power), H8 GND (power), H15 GND (power), J9 GND (power), J10 GND (power), J11 GND (power), J12 GND (power), J13 GND (power), J14 GND (power), K9 GND (power), K10 GND (power), K11 GND (power), K12 GND (power), K13 GND (power), K14 GND (power), L9 GND (power), L10 GND (power), L11 GND (power), L12 GND (power), L13 GND (power), L14 GND (power), M9 GND (power), M10 GND (power), M11 GND (power), M12 GND (power), M13 GND (power), M14 GND (power), N9 GND (power), N10 GND (power), N11 GND (power), N12 GND (power), N13 GND (power), N14 GND (power), P9 GND (power), P10 GND (power), P11 GND (power), P12 GND (power), P13 GND (power), P14 GND (power), R8 GND (power), R15 GND (power)
part L pins: A2 NC, A3 NC, A4 NC, A20 NC, A21 NC, AA3 NC, AA4 NC, AA5 NC, AA19 NC, AA20 NC, AB2 NC, AB3 NC, AB4 NC, AB20 NC, B1 NC, B2 NC, B3 NC, B4 NC, B5 NC, B19 NC, B20 NC, B21 NC, B22 NC, C1 NC, C2 NC, C3 NC, C4 NC, C5 NC, C6 NC, C16 NC, C17 NC, C18 NC, C19 NC, C20 NC, C21 NC, C22 NC, D1 NC, D2 NC, D3 NC, D5 NC, D6 NC, D16 NC, D17 NC, D18 NC, D20 NC, D21 NC, D22 NC, E1 NC, E2 NC, E3 NC, E5 NC, E6 NC, E7 NC, E8 NC, E16 NC, E17 NC, E18 NC, E20 NC, E21 NC, F1 NC, F2 NC, F3 NC, F4 NC, F5 NC, F6 NC, F7 NC, F15 NC, F16 NC, F17 NC, F18 NC, F19 NC, F20 NC, G3 NC, G4 NC, G5 NC, G6 NC, G17 NC, G18 NC, G19 NC, G20 NC, G21 NC, H4 NC, H5 NC, H6 NC, H17 NC, H18 NC, H19 NC, H20 NC, J5 NC, J18 NC, J19 NC, N20 NC, P3 NC, P4 NC, P5 NC, P18 NC, P19 NC, P20 NC, R1 NC, R2 NC, R3 NC, R4 NC, R5 NC, R6 NC, R17 NC, R18 NC, R19 NC, R21 NC, R22 NC, T1 NC, T2 NC, T3 NC, T6 NC, T17 NC, T18 NC, T22 NC, U6 NC, U7 NC, U15 NC, U16 NC, U17 NC, U22 NC, V6 NC, V7 NC, V8 NC, V16 NC, V17 NC, W5 NC, W6 NC, W16 NC, W17 NC, W18 NC, Y4 NC, Y5 NC, Y6 NC, Y16 NC, Y17 NC, Y18 NC, Y19 NC

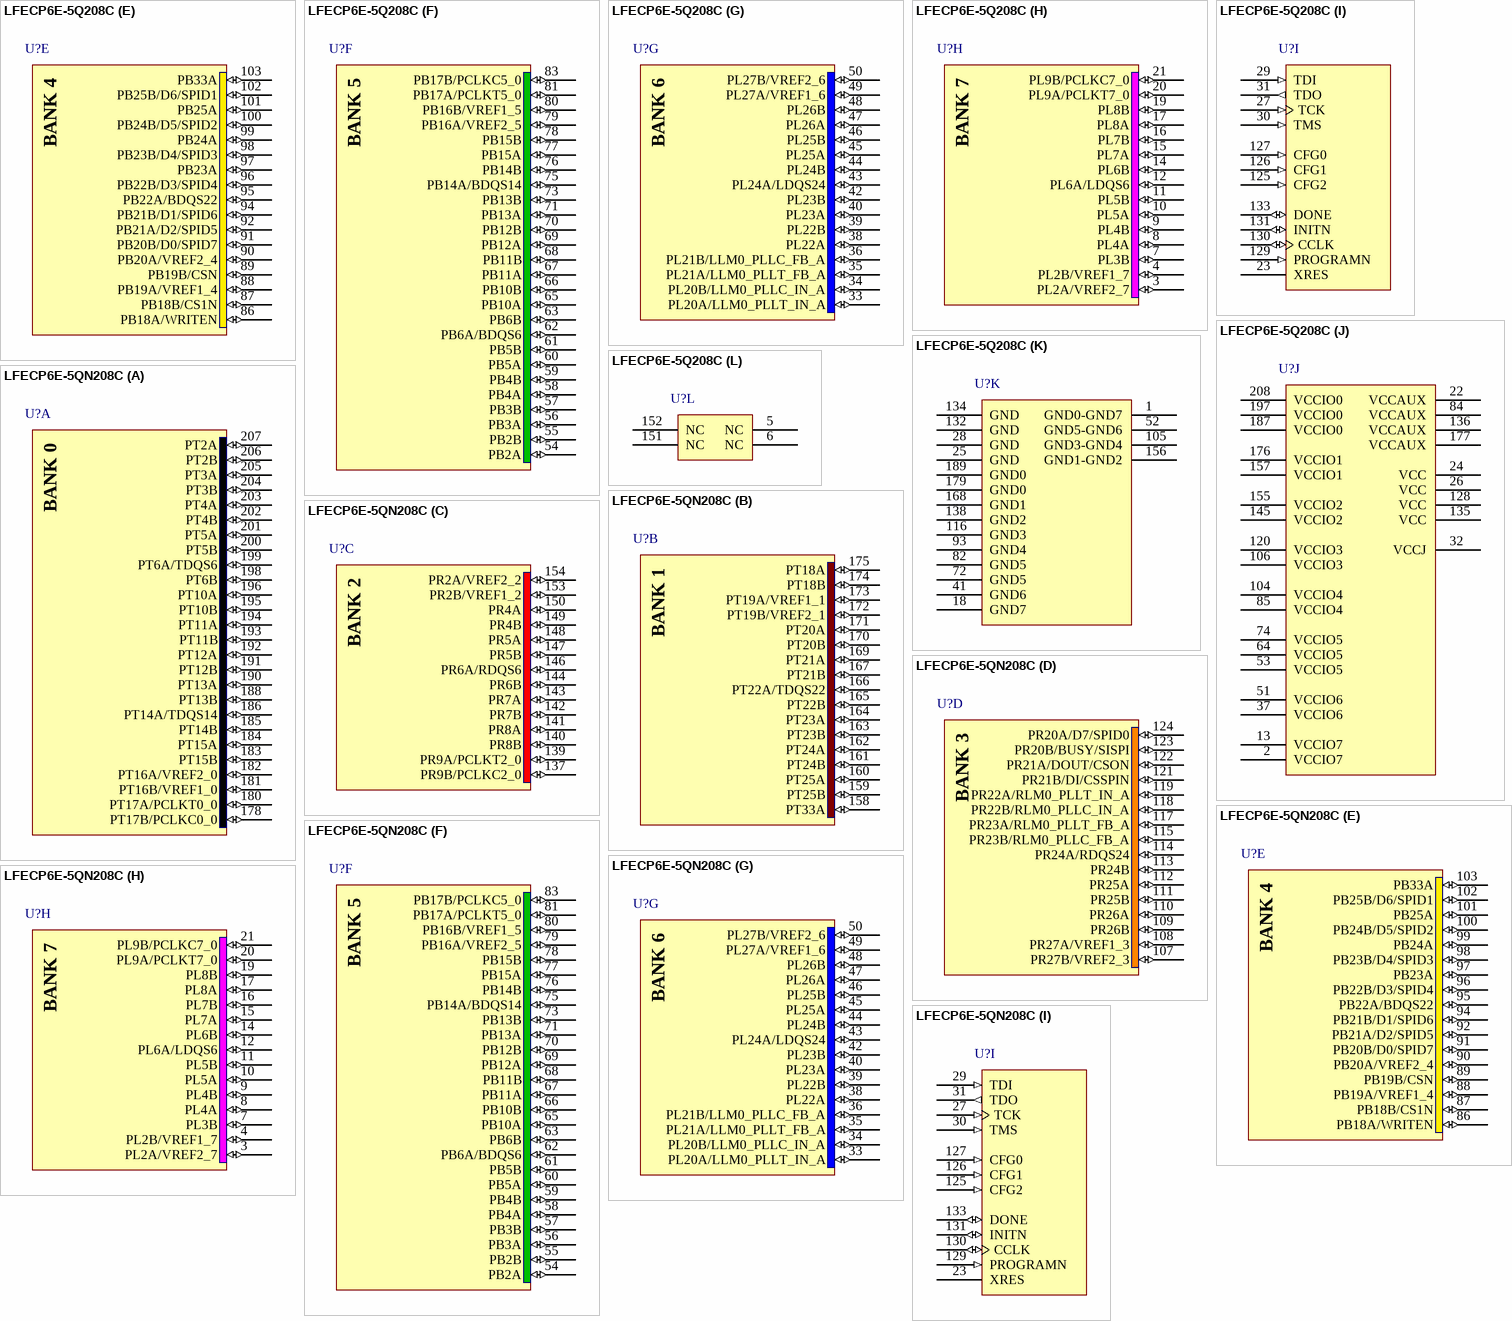
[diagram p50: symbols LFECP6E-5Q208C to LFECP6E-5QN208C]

## LFECP6E-5Q208C
designator U?
ECP 1.2V FPGA, 145 I/Os, 2 PLLs, 6.1K LUTs, 4 sysDSP Blocks, 16 18x18 Multipliers, 208-Pin PQFP, Speed Grade 5, Commercial Temperature Grade; Note: Pins 1, 52, 105 and 156 are double bonded.
footprint PQFP208_N (Shrink QFP, 208-Leads, Body 28x28mm, Pitch 0.5mm, IPC Medium Density)
footprint PQFP208_L (Shrink QFP, 208-Leads, Body 28x28mm, Pitch 0.5mm, IPC High Density)
footprint PQFP208_M (Shrink QFP, 208-Leads, Body 28x28mm, Pitch 0.5mm, IPC Low Density)
3D model ECP6E-PQFP-208 (208-Pin Plastic Quad Flat Pack (PQFP208))
part A pins: 178 PT17B/PCLKC0_0 (io), 180 PT17A/PCLKT0_0 (io), 181 PT16B/VREF1_0 (io), 182 PT16A/VREF2_0 (io), 183 PT15B (io), 184 PT15A (io), 185 PT14B (io), 186 PT14A/TDQS14 (io), 188 PT13B (io), 190 PT13A (io), 191 PT12B (io), 192 PT12A (io), 193 PT11B (io), 194 PT11A (io), 195 PT10B (io), 196 PT10A (io), 198 PT6B (io), 199 PT6A/TDQS6 (io), 200 PT5B (io), 201 PT5A (io), 202 PT4B (io), 203 PT4A (io), 204 PT3B (io), 205 PT3A (io), 206 PT2B (io), 207 PT2A (io)
part B pins: 158 PT33A (io), 159 PT25B (io), 160 PT25A (io), 161 PT24B (io), 162 PT24A (io), 163 PT23B (io), 164 PT23A (io), 165 PT22B (io), 166 PT22A/TDQS22 (io), 167 PT21B (io), 169 PT21A (io), 170 PT20B (io), 171 PT20A (io), 172 PT19B/VREF2_1 (io), 173 PT19A/VREF1_1 (io), 174 PT18B (io), 175 PT18A (io)
part C pins: 137 PR9B/PCLKC2_0 (io), 139 PR9A/PCLKT2_0 (io), 140 PR8B (io), 141 PR8A (io), 142 PR7B (io), 143 PR7A (io), 144 PR6B (io), 146 PR6A/RDQS6 (io), 147 PR5B (io), 148 PR5A (io), 149 PR4B (io), 150 PR4A (io), 153 PR2B/VREF1_2 (io), 154 PR2A/VREF2_2 (io)
part D pins: 107 PR27B/VREF2_3 (io), 108 PR27A/VREF1_3 (io), 109 PR26B (io), 110 PR26A (io), 111 PR25B (io), 112 PR25A (io), 113 PR24B (io), 114 PR24A/RDQS24 (io), 115 PR23B/RLM0_PLLC_FB_A (io), 117 PR23A/RLM0_PLLT_FB_A (io), 118 PR22B/RLM0_PLLC_IN_A (io), 119 PR22A/RLM0_PLLT_IN_A (io), 121 PR21B/DI/CSSPIN (io), 122 PR21A/DOUT/CSON (io), 123 PR20B/BUSY/SISPI (io), 124 PR20A/D7/SPID0 (io)
part E pins: 86 PB18A/WRITEN (io), 87 PB18B/CS1N (io), 88 PB19A/VREF1_4 (io), 89 PB19B/CSN (io), 90 PB20A/VREF2_4 (io), 91 PB20B/D0/SPID7 (io), 92 PB21A/D2/SPID5 (io), 94 PB21B/D1/SPID6 (io), 95 PB22A/BDQS22 (io), 96 PB22B/D3/SPID4 (io), 97 PB23A (io), 98 PB23B/D4/SPID3 (io), 99 PB24A (io), 100 PB24B/D5/SPID2 (io), 101 PB25A (io), 102 PB25B/D6/SPID1 (io), 103 PB33A (io)
part F pins: 54 PB2A (io), 55 PB2B (io), 56 PB3A (io), 57 PB3B (io), 58 PB4A (io), 59 PB4B (io), 60 PB5A (io), 61 PB5B (io), 62 PB6A/BDQS6 (io), 63 PB6B (io), 65 PB10A (io), 66 PB10B (io), 67 PB11A (io), 68 PB11B (io), 69 PB12A (io), 70 PB12B (io), 71 PB13A (io), 73 PB13B (io), 75 PB14A/BDQS14 (io), 76 PB14B (io), 77 PB15A (io), 78 PB15B (io), 79 PB16A/VREF2_5 (io), 80 PB16B/VREF1_5 (io), 81 PB17A/PCLKT5_0 (io), 83 PB17B/PCLKC5_0 (io)
part G pins: 33 PL20A/LLM0_PLLT_IN_A (io), 34 PL20B/LLM0_PLLC_IN_A (io), 35 PL21A/LLM0_PLLT_FB_A (io), 36 PL21B/LLM0_PLLC_FB_A (io), 38 PL22A (io), 39 PL22B (io), 40 PL23A (io), 42 PL23B (io), 43 PL24A/LDQS24 (io), 44 PL24B (io), 45 PL25A (io), 46 PL25B (io), 47 PL26A (io), 48 PL26B (io), 49 PL27A/VREF1_6 (io), 50 PL27B/VREF2_6 (io)
part H pins: 3 PL2A/VREF2_7 (io), 4 PL2B/VREF1_7 (io), 7 PL3B (io), 8 PL4A (io), 9 PL4B (io), 10 PL5A (io), 11 PL5B (io), 12 PL6A/LDQS6 (io), 14 PL6B (io), 15 PL7A (io), 16 PL7B (io), 17 PL8A (io), 19 PL8B (io), 20 PL9A/PCLKT7_0 (io), 21 PL9B/PCLKC7_0 (io)
part I pins: 23 XRES, 27 TCK (in), 29 TDI (in), 30 TMS (in), 31 TDO (out), 125 CFG2 (in), 126 CFG1 (in), 127 CFG0 (in), 129 PROGRAMN (in), 130 CCLK (io), 131 INITN (io), 133 DONE (io)
part J pins: 2 VCCIO7 (power), 13 VCCIO7 (power), 22 VCCAUX (power), 24 VCC (power), 26 VCC (power), 32 VCCJ (power), 37 VCCIO6 (power), 51 VCCIO6 (power), 53 VCCIO5 (power), 64 VCCIO5 (power), 74 VCCIO5 (power), 84 VCCAUX (power), 85 VCCIO4 (power), 104 VCCIO4 (power), 106 VCCIO3 (power), 120 VCCIO3 (power), 128 VCC (power), 135 VCC (power), 136 VCCAUX (power), 145 VCCIO2 (power), 155 VCCIO2 (power), 157 VCCIO1 (power), 176 VCCIO1 (power), 177 VCCAUX (power), 187 VCCIO0 (power), 197 VCCIO0 (power), 208 VCCIO0 (power)
part K pins: 1 GND0-GND7 (power), 18 GND7 (power), 25 GND (power), 28 GND (power), 41 GND6 (power), 52 GND5-GND6 (power), 72 GND5 (power), 82 GND5 (power), 93 GND4 (power), 105 GND3-GND4 (power), 116 GND3 (power), 132 GND (power), 134 GND (power), 138 GND2 (power), 156 GND1-GND2 (power), 168 GND1 (power), 179 GND0 (power), 189 GND0 (power)
part L pins: 5 NC, 6 NC, 151 NC, 152 NC

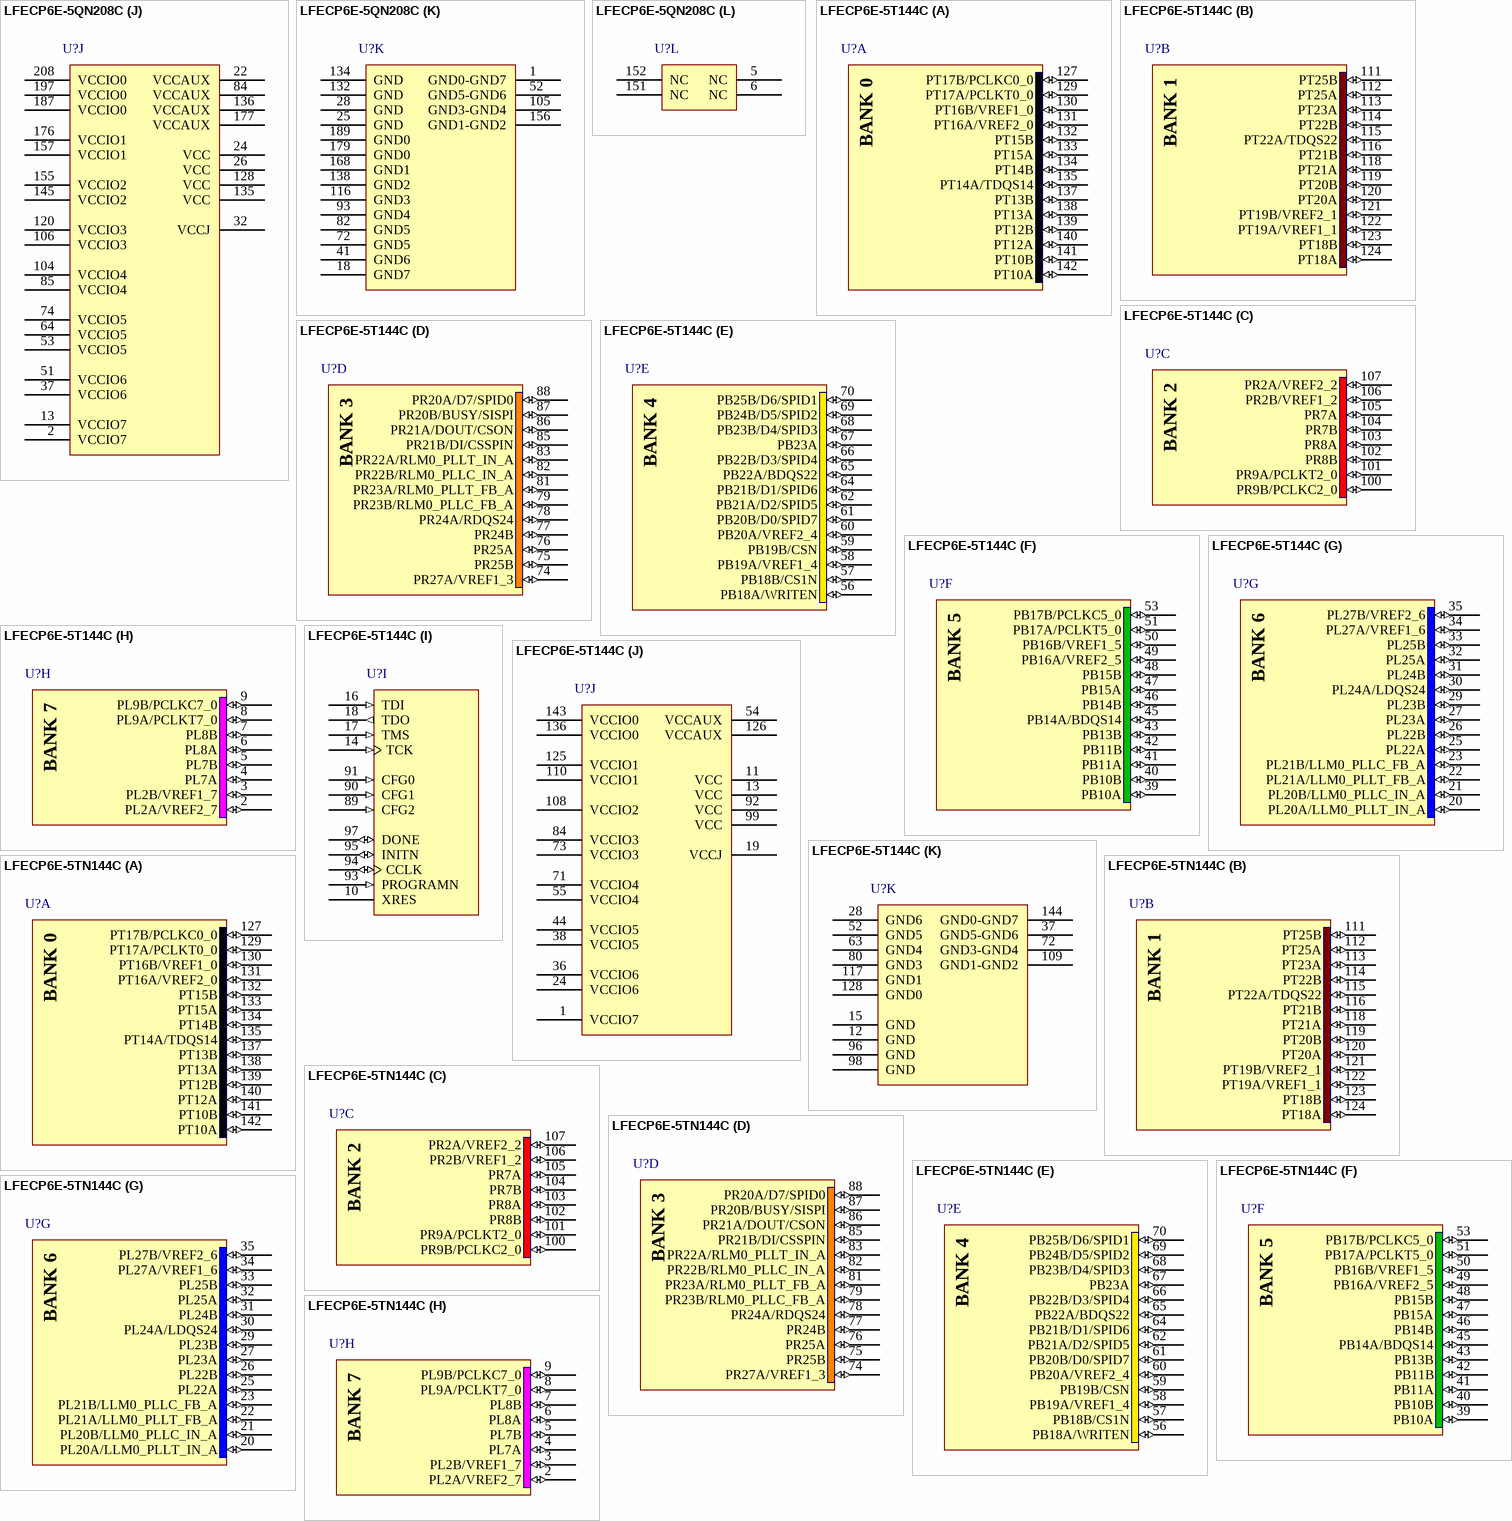
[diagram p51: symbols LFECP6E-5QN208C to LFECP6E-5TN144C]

## LFECP6E-5QN208C
designator U?
ECP 1.2V FPGA, 147 I/Os, 2 PLLs, 6.1K LUTs, 4 sysDSP Blocks, 16 18x18 Multipliers, 208-Pin PQFP, Pb-Free, Speed Grade 5, Commercial Temperature Grade; Note: Pins 1, 52, 105 and 156 are double bonded.
footprint PQFP208_N (Shrink QFP, 208-Leads, Body 28x28mm, Pitch 0.5mm, IPC Medium Density)
footprint PQFP208_L (Shrink QFP, 208-Leads, Body 28x28mm, Pitch 0.5mm, IPC High Density)
footprint PQFP208_M (Shrink QFP, 208-Leads, Body 28x28mm, Pitch 0.5mm, IPC Low Density)
3D model ECP6E-PQFP-208 (208-Pin Plastic Quad Flat Pack (PQFP208))
part A pins: 178 PT17B/PCLKC0_0 (io), 180 PT17A/PCLKT0_0 (io), 181 PT16B/VREF1_0 (io), 182 PT16A/VREF2_0 (io), 183 PT15B (io), 184 PT15A (io), 185 PT14B (io), 186 PT14A/TDQS14 (io), 188 PT13B (io), 190 PT13A (io), 191 PT12B (io), 192 PT12A (io), 193 PT11B (io), 194 PT11A (io), 195 PT10B (io), 196 PT10A (io), 198 PT6B (io), 199 PT6A/TDQS6 (io), 200 PT5B (io), 201 PT5A (io), 202 PT4B (io), 203 PT4A (io), 204 PT3B (io), 205 PT3A (io), 206 PT2B (io), 207 PT2A (io)
part B pins: 158 PT33A (io), 159 PT25B (io), 160 PT25A (io), 161 PT24B (io), 162 PT24A (io), 163 PT23B (io), 164 PT23A (io), 165 PT22B (io), 166 PT22A/TDQS22 (io), 167 PT21B (io), 169 PT21A (io), 170 PT20B (io), 171 PT20A (io), 172 PT19B/VREF2_1 (io), 173 PT19A/VREF1_1 (io), 174 PT18B (io), 175 PT18A (io)
part C pins: 137 PR9B/PCLKC2_0 (io), 139 PR9A/PCLKT2_0 (io), 140 PR8B (io), 141 PR8A (io), 142 PR7B (io), 143 PR7A (io), 144 PR6B (io), 146 PR6A/RDQS6 (io), 147 PR5B (io), 148 PR5A (io), 149 PR4B (io), 150 PR4A (io), 153 PR2B/VREF1_2 (io), 154 PR2A/VREF2_2 (io)
part D pins: 107 PR27B/VREF2_3 (io), 108 PR27A/VREF1_3 (io), 109 PR26B (io), 110 PR26A (io), 111 PR25B (io), 112 PR25A (io), 113 PR24B (io), 114 PR24A/RDQS24 (io), 115 PR23B/RLM0_PLLC_FB_A (io), 117 PR23A/RLM0_PLLT_FB_A (io), 118 PR22B/RLM0_PLLC_IN_A (io), 119 PR22A/RLM0_PLLT_IN_A (io), 121 PR21B/DI/CSSPIN (io), 122 PR21A/DOUT/CSON (io), 123 PR20B/BUSY/SISPI (io), 124 PR20A/D7/SPID0 (io)
part E pins: 86 PB18A/WRITEN (io), 87 PB18B/CS1N (io), 88 PB19A/VREF1_4 (io), 89 PB19B/CSN (io), 90 PB20A/VREF2_4 (io), 91 PB20B/D0/SPID7 (io), 92 PB21A/D2/SPID5 (io), 94 PB21B/D1/SPID6 (io), 95 PB22A/BDQS22 (io), 96 PB22B/D3/SPID4 (io), 97 PB23A (io), 98 PB23B/D4/SPID3 (io), 99 PB24A (io), 100 PB24B/D5/SPID2 (io), 101 PB25A (io), 102 PB25B/D6/SPID1 (io), 103 PB33A (io)
part F pins: 54 PB2A (io), 55 PB2B (io), 56 PB3A (io), 57 PB3B (io), 58 PB4A (io), 59 PB4B (io), 60 PB5A (io), 61 PB5B (io), 62 PB6A/BDQS6 (io), 63 PB6B (io), 65 PB10A (io), 66 PB10B (io), 67 PB11A (io), 68 PB11B (io), 69 PB12A (io), 70 PB12B (io), 71 PB13A (io), 73 PB13B (io), 75 PB14A/BDQS14 (io), 76 PB14B (io), 77 PB15A (io), 78 PB15B (io), 79 PB16A/VREF2_5 (io), 80 PB16B/VREF1_5 (io), 81 PB17A/PCLKT5_0 (io), 83 PB17B/PCLKC5_0 (io)
part G pins: 33 PL20A/LLM0_PLLT_IN_A (io), 34 PL20B/LLM0_PLLC_IN_A (io), 35 PL21A/LLM0_PLLT_FB_A (io), 36 PL21B/LLM0_PLLC_FB_A (io), 38 PL22A (io), 39 PL22B (io), 40 PL23A (io), 42 PL23B (io), 43 PL24A/LDQS24 (io), 44 PL24B (io), 45 PL25A (io), 46 PL25B (io), 47 PL26A (io), 48 PL26B (io), 49 PL27A/VREF1_6 (io), 50 PL27B/VREF2_6 (io)
part H pins: 3 PL2A/VREF2_7 (io), 4 PL2B/VREF1_7 (io), 7 PL3B (io), 8 PL4A (io), 9 PL4B (io), 10 PL5A (io), 11 PL5B (io), 12 PL6A/LDQS6 (io), 14 PL6B (io), 15 PL7A (io), 16 PL7B (io), 17 PL8A (io), 19 PL8B (io), 20 PL9A/PCLKT7_0 (io), 21 PL9B/PCLKC7_0 (io)
part I pins: 23 XRES, 27 TCK (in), 29 TDI (in), 30 TMS (in), 31 TDO (out), 125 CFG2 (in), 126 CFG1 (in), 127 CFG0 (in), 129 PROGRAMN (in), 130 CCLK (io), 131 INITN (io), 133 DONE (io)
part J pins: 2 VCCIO7 (power), 13 VCCIO7 (power), 22 VCCAUX (power), 24 VCC (power), 26 VCC (power), 32 VCCJ (power), 37 VCCIO6 (power), 51 VCCIO6 (power), 53 VCCIO5 (power), 64 VCCIO5 (power), 74 VCCIO5 (power), 84 VCCAUX (power), 85 VCCIO4 (power), 104 VCCIO4 (power), 106 VCCIO3 (power), 120 VCCIO3 (power), 128 VCC (power), 135 VCC (power), 136 VCCAUX (power), 145 VCCIO2 (power), 155 VCCIO2 (power), 157 VCCIO1 (power), 176 VCCIO1 (power), 177 VCCAUX (power), 187 VCCIO0 (power), 197 VCCIO0 (power), 208 VCCIO0 (power)
part K pins: 1 GND0-GND7 (power), 18 GND7 (power), 25 GND (power), 28 GND (power), 41 GND6 (power), 52 GND5-GND6 (power), 72 GND5 (power), 82 GND5 (power), 93 GND4 (power), 105 GND3-GND4 (power), 116 GND3 (power), 132 GND (power), 134 GND (power), 138 GND2 (power), 156 GND1-GND2 (power), 168 GND1 (power), 179 GND0 (power), 189 GND0 (power)
part L pins: 5 NC, 6 NC, 151 NC, 152 NC

## LFECP6E-5T144C
designator U?
ECP 1.2V FPGA, 97 I/Os, 2 PLLs, 6.1K LUTs, 4 sysDSP Blocks, 16 18x18 Multipliers, 144-Pin TQFP, Speed Grade 5, Commercial Temperature Grade; Note: Pins 37, 72, 109 and 144 are double bonded.
footprint TQFP144_N (Thin QFP, 144-Leads, Body 20x20mm, Pitch 0.5mm, IPC Medium Density)
footprint TQFP144_L (Thin QFP, 144-Leads, Body 20x20mm, Pitch 0.5mm, IPC High Density)
footprint TQFP144_M (Thin QFP, 144-Leads, Body 20x20mm, Pitch 0.5mm, IPC Low Density)
3D model ECP6E-TQFP-144 (144-Pin Thin Quad Flat Pack (TQFP144))
part A pins: 127 PT17B/PCLKC0_0 (io), 129 PT17A/PCLKT0_0 (io), 130 PT16B/VREF1_0 (io), 131 PT16A/VREF2_0 (io), 132 PT15B (io), 133 PT15A (io), 134 PT14B (io), 135 PT14A/TDQS14 (io), 137 PT13B (io), 138 PT13A (io), 139 PT12B (io), 140 PT12A (io), 141 PT10B (io), 142 PT10A (io)
part B pins: 111 PT25B (io), 112 PT25A (io), 113 PT23A (io), 114 PT22B (io), 115 PT22A/TDQS22 (io), 116 PT21B (io), 118 PT21A (io), 119 PT20B (io), 120 PT20A (io), 121 PT19B/VREF2_1 (io), 122 PT19A/VREF1_1 (io), 123 PT18B (io), 124 PT18A (io)
part C pins: 100 PR9B/PCLKC2_0 (io), 101 PR9A/PCLKT2_0 (io), 102 PR8B (io), 103 PR8A (io), 104 PR7B (io), 105 PR7A (io), 106 PR2B/VREF1_2 (io), 107 PR2A/VREF2_2 (io)
part D pins: 74 PR27A/VREF1_3 (io), 75 PR25B (io), 76 PR25A (io), 77 PR24B (io), 78 PR24A/RDQS24 (io), 79 PR23B/RLM0_PLLC_FB_A (io), 81 PR23A/RLM0_PLLT_FB_A (io), 82 PR22B/RLM0_PLLC_IN_A (io), 83 PR22A/RLM0_PLLT_IN_A (io), 85 PR21B/DI/CSSPIN (io), 86 PR21A/DOUT/CSON (io), 87 PR20B/BUSY/SISPI (io), 88 PR20A/D7/SPID0 (io)
part E pins: 56 PB18A/WRITEN (io), 57 PB18B/CS1N (io), 58 PB19A/VREF1_4 (io), 59 PB19B/CSN (io), 60 PB20A/VREF2_4 (io), 61 PB20B/D0/SPID7 (io), 62 PB21A/D2/SPID5 (io), 64 PB21B/D1/SPID6 (io), 65 PB22A/BDQS22 (io), 66 PB22B/D3/SPID4 (io), 67 PB23A (io), 68 PB23B/D4/SPID3 (io), 69 PB24B/D5/SPID2 (io), 70 PB25B/D6/SPID1 (io)
part F pins: 39 PB10A (io), 40 PB10B (io), 41 PB11A (io), 42 PB11B (io), 43 PB13B (io), 45 PB14A/BDQS14 (io), 46 PB14B (io), 47 PB15A (io), 48 PB15B (io), 49 PB16A/VREF2_5 (io), 50 PB16B/VREF1_5 (io), 51 PB17A/PCLKT5_0 (io), 53 PB17B/PCLKC5_0 (io)
part G pins: 20 PL20A/LLM0_PLLT_IN_A (io), 21 PL20B/LLM0_PLLC_IN_A (io), 22 PL21A/LLM0_PLLT_FB_A (io), 23 PL21B/LLM0_PLLC_FB_A (io), 25 PL22A (io), 26 PL22B (io), 27 PL23A (io), 29 PL23B (io), 30 PL24A/LDQS24 (io), 31 PL24B (io), 32 PL25A (io), 33 PL25B (io), 34 PL27A/VREF1_6 (io), 35 PL27B/VREF2_6 (io)
part H pins: 2 PL2A/VREF2_7 (io), 3 PL2B/VREF1_7 (io), 4 PL7A (io), 5 PL7B (io), 6 PL8A (io), 7 PL8B (io), 8 PL9A/PCLKT7_0 (io), 9 PL9B/PCLKC7_0 (io)
part I pins: 10 XRES, 14 TCK (in), 16 TDI (in), 17 TMS (in), 18 TDO (out), 89 CFG2 (in), 90 CFG1 (in), 91 CFG0 (in), 93 PROGRAMN (in), 94 CCLK (io), 95 INITN (io), 97 DONE (io)
part J pins: 1 VCCIO7 (power), 11 VCC (power), 13 VCC (power), 19 VCCJ (power), 24 VCCIO6 (power), 36 VCCIO6 (power), 38 VCCIO5 (power), 44 VCCIO5 (power), 54 VCCAUX (power), 55 VCCIO4 (power), 71 VCCIO4 (power), 73 VCCIO3 (power), 84 VCCIO3 (power), 92 VCC (power), 99 VCC (power), 108 VCCIO2 (power), 110 VCCIO1 (power), 125 VCCIO1 (power), 126 VCCAUX (power), 136 VCCIO0 (power), 143 VCCIO0 (power)
part K pins: 12 GND (power), 15 GND (power), 28 GND6 (power), 37 GND5-GND6 (power), 52 GND5 (power), 63 GND4 (power), 72 GND3-GND4 (power), 80 GND3 (power), 96 GND (power), 98 GND (power), 109 GND1-GND2 (power), 117 GND1 (power), 128 GND0 (power), 144 GND0-GND7 (power)

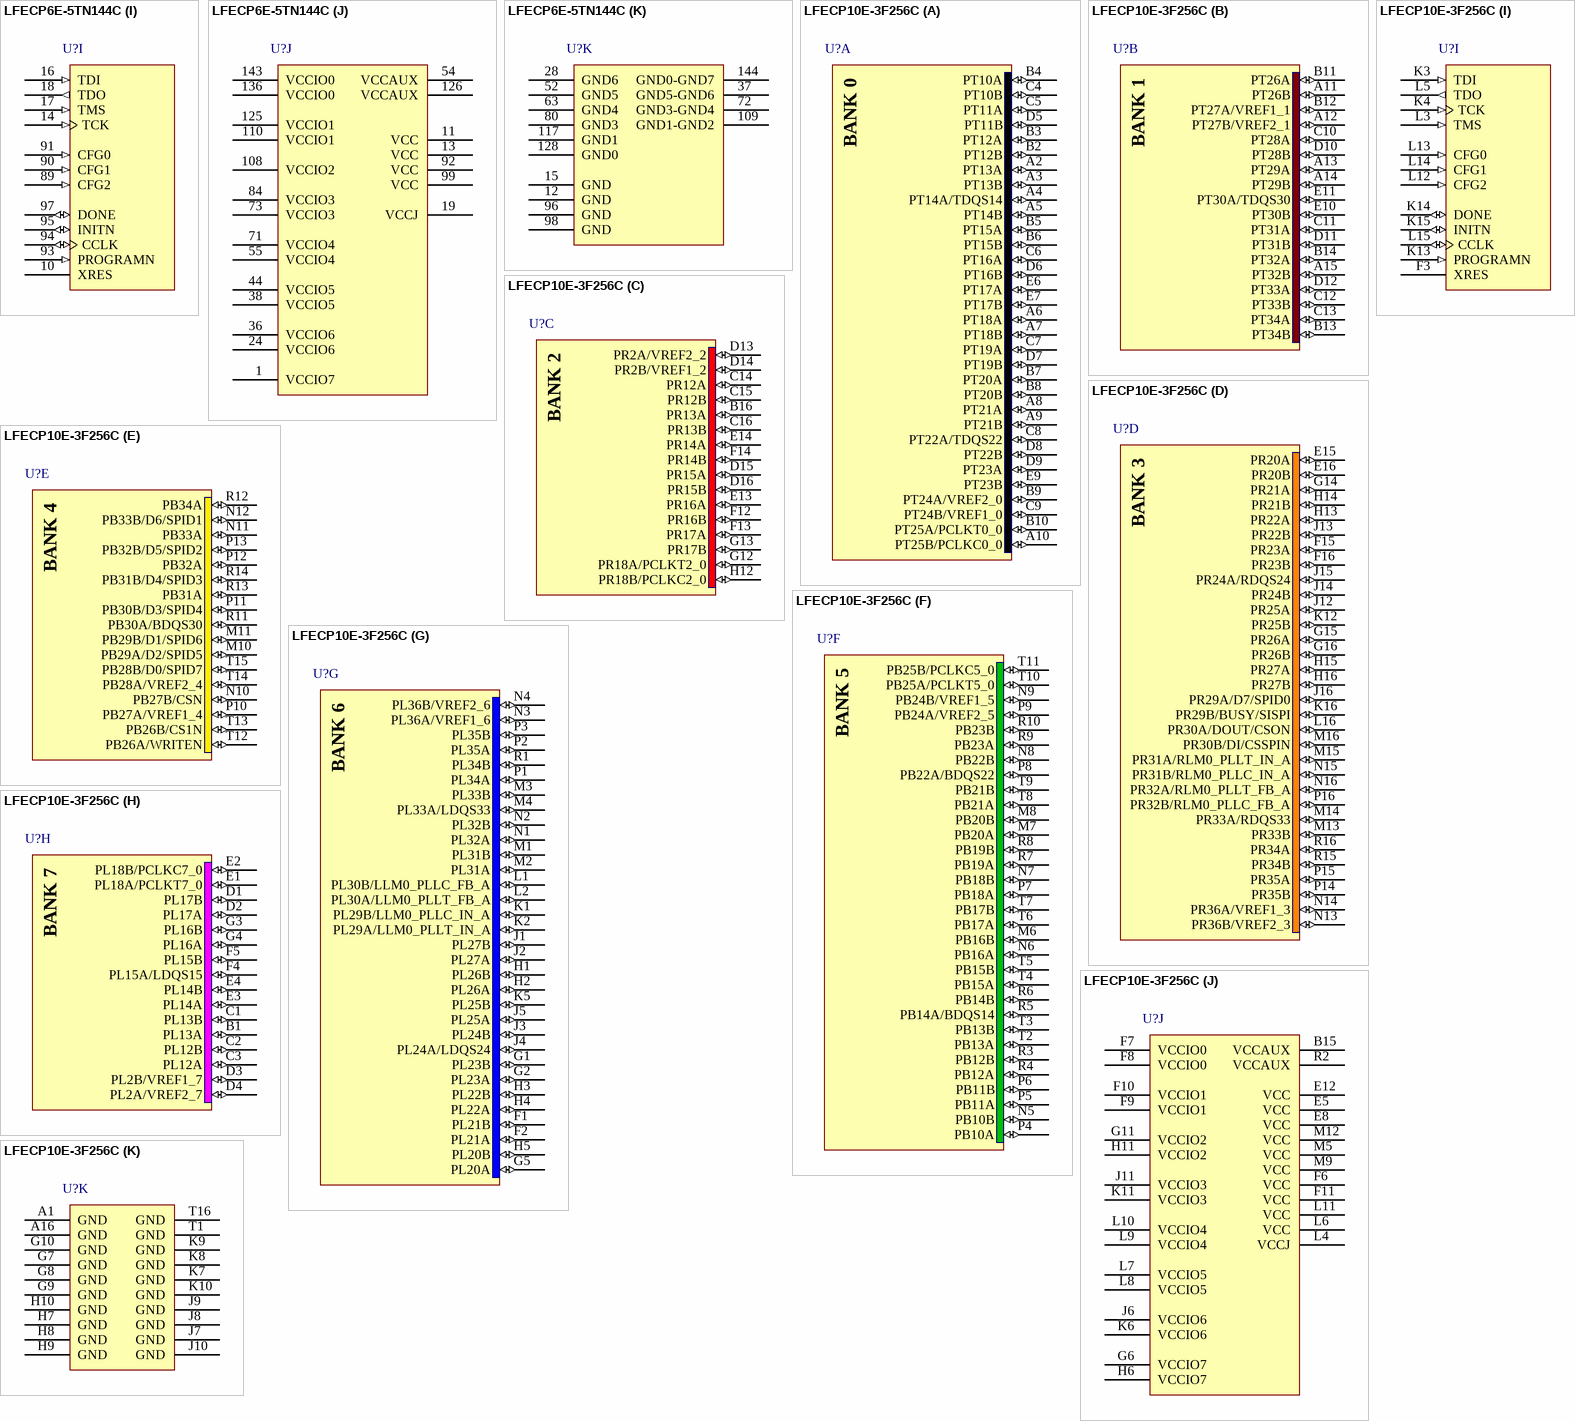
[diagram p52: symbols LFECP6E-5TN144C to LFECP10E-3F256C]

## LFECP6E-5TN144C
designator U?
ECP 1.2V FPGA, 97 I/Os, 2 PLLs, 6.1K LUTs, 4 sysDSP Blocks, 16 18x18 Multipliers, 144-Pin TQFP, Pb-Free, Speed Grade 5, Commercial Temperature Grade; Note: Pins 37, 72, 109 and 144 are double bonded.
footprint TQFP144_N (Thin QFP, 144-Leads, Body 20x20mm, Pitch 0.5mm, IPC Medium Density)
footprint TQFP144_L (Thin QFP, 144-Leads, Body 20x20mm, Pitch 0.5mm, IPC High Density)
footprint TQFP144_M (Thin QFP, 144-Leads, Body 20x20mm, Pitch 0.5mm, IPC Low Density)
3D model ECP6E-TQFP-144 (144-Pin Thin Quad Flat Pack (TQFP144))
part A pins: 127 PT17B/PCLKC0_0 (io), 129 PT17A/PCLKT0_0 (io), 130 PT16B/VREF1_0 (io), 131 PT16A/VREF2_0 (io), 132 PT15B (io), 133 PT15A (io), 134 PT14B (io), 135 PT14A/TDQS14 (io), 137 PT13B (io), 138 PT13A (io), 139 PT12B (io), 140 PT12A (io), 141 PT10B (io), 142 PT10A (io)
part B pins: 111 PT25B (io), 112 PT25A (io), 113 PT23A (io), 114 PT22B (io), 115 PT22A/TDQS22 (io), 116 PT21B (io), 118 PT21A (io), 119 PT20B (io), 120 PT20A (io), 121 PT19B/VREF2_1 (io), 122 PT19A/VREF1_1 (io), 123 PT18B (io), 124 PT18A (io)
part C pins: 100 PR9B/PCLKC2_0 (io), 101 PR9A/PCLKT2_0 (io), 102 PR8B (io), 103 PR8A (io), 104 PR7B (io), 105 PR7A (io), 106 PR2B/VREF1_2 (io), 107 PR2A/VREF2_2 (io)
part D pins: 74 PR27A/VREF1_3 (io), 75 PR25B (io), 76 PR25A (io), 77 PR24B (io), 78 PR24A/RDQS24 (io), 79 PR23B/RLM0_PLLC_FB_A (io), 81 PR23A/RLM0_PLLT_FB_A (io), 82 PR22B/RLM0_PLLC_IN_A (io), 83 PR22A/RLM0_PLLT_IN_A (io), 85 PR21B/DI/CSSPIN (io), 86 PR21A/DOUT/CSON (io), 87 PR20B/BUSY/SISPI (io), 88 PR20A/D7/SPID0 (io)
part E pins: 56 PB18A/WRITEN (io), 57 PB18B/CS1N (io), 58 PB19A/VREF1_4 (io), 59 PB19B/CSN (io), 60 PB20A/VREF2_4 (io), 61 PB20B/D0/SPID7 (io), 62 PB21A/D2/SPID5 (io), 64 PB21B/D1/SPID6 (io), 65 PB22A/BDQS22 (io), 66 PB22B/D3/SPID4 (io), 67 PB23A (io), 68 PB23B/D4/SPID3 (io), 69 PB24B/D5/SPID2 (io), 70 PB25B/D6/SPID1 (io)
part F pins: 39 PB10A (io), 40 PB10B (io), 41 PB11A (io), 42 PB11B (io), 43 PB13B (io), 45 PB14A/BDQS14 (io), 46 PB14B (io), 47 PB15A (io), 48 PB15B (io), 49 PB16A/VREF2_5 (io), 50 PB16B/VREF1_5 (io), 51 PB17A/PCLKT5_0 (io), 53 PB17B/PCLKC5_0 (io)
part G pins: 20 PL20A/LLM0_PLLT_IN_A (io), 21 PL20B/LLM0_PLLC_IN_A (io), 22 PL21A/LLM0_PLLT_FB_A (io), 23 PL21B/LLM0_PLLC_FB_A (io), 25 PL22A (io), 26 PL22B (io), 27 PL23A (io), 29 PL23B (io), 30 PL24A/LDQS24 (io), 31 PL24B (io), 32 PL25A (io), 33 PL25B (io), 34 PL27A/VREF1_6 (io), 35 PL27B/VREF2_6 (io)
part H pins: 2 PL2A/VREF2_7 (io), 3 PL2B/VREF1_7 (io), 4 PL7A (io), 5 PL7B (io), 6 PL8A (io), 7 PL8B (io), 8 PL9A/PCLKT7_0 (io), 9 PL9B/PCLKC7_0 (io)
part I pins: 10 XRES, 14 TCK (in), 16 TDI (in), 17 TMS (in), 18 TDO (out), 89 CFG2 (in), 90 CFG1 (in), 91 CFG0 (in), 93 PROGRAMN (in), 94 CCLK (io), 95 INITN (io), 97 DONE (io)
part J pins: 1 VCCIO7 (power), 11 VCC (power), 13 VCC (power), 19 VCCJ (power), 24 VCCIO6 (power), 36 VCCIO6 (power), 38 VCCIO5 (power), 44 VCCIO5 (power), 54 VCCAUX (power), 55 VCCIO4 (power), 71 VCCIO4 (power), 73 VCCIO3 (power), 84 VCCIO3 (power), 92 VCC (power), 99 VCC (power), 108 VCCIO2 (power), 110 VCCIO1 (power), 125 VCCIO1 (power), 126 VCCAUX (power), 136 VCCIO0 (power), 143 VCCIO0 (power)
part K pins: 12 GND (power), 15 GND (power), 28 GND6 (power), 37 GND5-GND6 (power), 52 GND5 (power), 63 GND4 (power), 72 GND3-GND4 (power), 80 GND3 (power), 96 GND (power), 98 GND (power), 109 GND1-GND2 (power), 117 GND1 (power), 128 GND0 (power), 144 GND0-GND7 (power)

## LFECP10E-3F256C
designator U?
ECP 1.2V FPGA, 192 I/Os, 4 PLLs, 10.2K LUTs, 5 sysDSP Blocks, 20 18x18 Multipliers, 256-Pin fpBGA, Speed Grade 3, Commercial Temperature Grade
footprint fpBGA256 (BGA, 256-Leads, Body 17x17mm, Pitch 1mm)
3D model ECP10E-fpBGA256 (256-Ball Fine Pitch Ball Grid Array (fpBGA256))
part A pins: A2 PT13A (io), A3 PT13B (io), A4 PT14A/TDQS14 (io), A5 PT14B (io), A6 PT18A (io), A7 PT18B (io), A8 PT21A (io), A9 PT21B (io), A10 PT25B/PCLKC0_0 (io), B2 PT12B (io), B3 PT12A (io), B4 PT10A (io), B5 PT15A (io), B6 PT15B (io), B7 PT20A (io), B8 PT20B (io), B9 PT24A/VREF2_0 (io), B10 PT25A/PCLKT0_0 (io), C4 PT10B (io), C5 PT11A (io), C6 PT16A (io), C7 PT19A (io), C8 PT22A/TDQS22 (io), C9 PT24B/VREF1_0 (io), D5 PT11B (io), D6 PT16B (io), D7 PT19B (io), D8 PT22B (io), D9 PT23A (io), E6 PT17A (io), E7 PT17B (io), E9 PT23B (io)
part B pins: A11 PT26B (io), A12 PT27B/VREF2_1 (io), A13 PT29A (io), A14 PT29B (io), A15 PT32B (io), B11 PT26A (io), B12 PT27A/VREF1_1 (io), B13 PT34B (io), B14 PT32A (io), C10 PT28A (io), C11 PT31A (io), C12 PT33B (io), C13 PT34A (io), D10 PT28B (io), D11 PT31B (io), D12 PT33A (io), E10 PT30B (io), E11 PT30A/TDQS30 (io)
part C pins: B16 PR13A (io), C14 PR12A (io), C15 PR12B (io), C16 PR13B (io), D13 PR2A/VREF2_2 (io), D14 PR2B/VREF1_2 (io), D15 PR15A (io), D16 PR15B (io), E13 PR16A (io), E14 PR14A (io), F12 PR16B (io), F13 PR17A (io), F14 PR14B (io), G12 PR18A/PCLKT2_0 (io), G13 PR17B (io), H12 PR18B/PCLKC2_0 (io)
part D pins: E15 PR20A (io), E16 PR20B (io), F15 PR23A (io), F16 PR23B (io), G14 PR21A (io), G15 PR26A (io), G16 PR26B (io), H13 PR22A (io), H14 PR21B (io), H15 PR27A (io), H16 PR27B (io), J12 PR25A (io), J13 PR22B (io), J14 PR24B (io), J15 PR24A/RDQS24 (io), J16 PR29A/D7/SPID0 (io), K12 PR25B (io), K16 PR29B/BUSY/SISPI (io), L16 PR30A/DOUT/CSON (io), M13 PR33B (io), M14 PR33A/RDQS33 (io), M15 PR31A/RLM0_PLLT_IN_A (io), M16 PR30B/DI/CSSPIN (io), N13 PR36B/VREF2_3 (io), N14 PR36A/VREF1_3 (io), N15 PR31B/RLM0_PLLC_IN_A (io), N16 PR32A/RLM0_PLLT_FB_A (io), P14 PR35B (io), P15 PR35A (io), P16 PR32B/RLM0_PLLC_FB_A (io), R15 PR34B (io), R16 PR34A (io)
part E pins: M10 PB29A/D2/SPID5 (io), M11 PB29B/D1/SPID6 (io), N10 PB27B/CSN (io), N11 PB33A (io), N12 PB33B/D6/SPID1 (io), P10 PB27A/VREF1_4 (io), P11 PB30B/D3/SPID4 (io), P12 PB32A (io), P13 PB32B/D5/SPID2 (io), R11 PB30A/BDQS30 (io), R12 PB34A (io), R13 PB31A (io), R14 PB31B/D4/SPID3 (io), T12 PB26A/WRITEN (io), T13 PB26B/CS1N (io), T14 PB28A/VREF2_4 (io), T15 PB28B/D0/SPID7 (io)
part F pins: M6 PB16B (io), M7 PB20A (io), M8 PB20B (io), N5 PB10B (io), N6 PB16A (io), N7 PB18B (io), N8 PB22B (io), N9 PB24B/VREF1_5 (io), P4 PB10A (io), P5 PB11A (io), P6 PB11B (io), P7 PB18A (io), P8 PB22A/BDQS22 (io), P9 PB24A/VREF2_5 (io), R3 PB12B (io), R4 PB12A (io), R5 PB14A/BDQS14 (io), R6 PB14B (io), R7 PB19A (io), R8 PB19B (io), R9 PB23A (io), R10 PB23B (io), T2 PB13A (io), T3 PB13B (io), T4 PB15A (io), T5 PB15B (io), T6 PB17A (io), T7 PB17B (io), T8 PB21A (io), T9 PB21B (io), T10 PB25A/PCLKT5_0 (io), T11 PB25B/PCLKC5_0 (io)
part G pins: F1 PL21B (io), F2 PL21A (io), G1 PL23B (io), G2 PL23A (io), G5 PL20A (io), H1 PL26B (io), H2 PL26A (io), H3 PL22B (io), H4 PL22A (io), H5 PL20B (io), J1 PL27B (io), J2 PL27A (io), J3 PL24B (io), J4 PL24A/LDQS24 (io), J5 PL25A (io), K1 PL29B/LLM0_PLLC_IN_A (io), K2 PL29A/LLM0_PLLT_IN_A (io), K5 PL25B (io), L1 PL30B/LLM0_PLLC_FB_A (io), L2 PL30A/LLM0_PLLT_FB_A (io), M1 PL31B (io), M2 PL31A (io), M3 PL33B (io), M4 PL33A/LDQS33 (io), N1 PL32A (io), N2 PL32B (io), N3 PL36A/VREF1_6 (io), N4 PL36B/VREF2_6 (io), P1 PL34A (io), P2 PL35A (io), P3 PL35B (io), R1 PL34B (io)
part H pins: B1 PL13A (io), C1 PL13B (io), C2 PL12B (io), C3 PL12A (io), D1 PL17B (io), D2 PL17A (io), D3 PL2B/VREF1_7 (io), D4 PL2A/VREF2_7 (io), E1 PL18A/PCLKT7_0 (io), E2 PL18B/PCLKC7_0 (io), E3 PL14A (io), E4 PL14B (io), F4 PL15A/LDQS15 (io), F5 PL15B (io), G3 PL16B (io), G4 PL16A (io)
part I pins: F3 XRES, K3 TDI (in), K4 TCK (in), K13 PROGRAMN (in), K14 DONE (io), K15 INITN (io), L3 TMS (in), L5 TDO (out), L12 CFG2 (in), L13 CFG0 (in), L14 CFG1 (in), L15 CCLK (io)
part J pins: B15 VCCAUX (power), E5 VCC (power), E8 VCC (power), E12 VCC (power), F6 VCC (power), F7 VCCIO0 (power), F8 VCCIO0 (power), F9 VCCIO1 (power), F10 VCCIO1 (power), F11 VCC (power), G6 VCCIO7 (power), G11 VCCIO2 (power), H6 VCCIO7 (power), H11 VCCIO2 (power), J6 VCCIO6 (power), J11 VCCIO3 (power), K6 VCCIO6 (power), K11 VCCIO3 (power), L4 VCCJ (power), L6 VCC (power), L7 VCCIO5 (power), L8 VCCIO5 (power), L9 VCCIO4 (power), L10 VCCIO4 (power), L11 VCC (power), M5 VCC (power), M9 VCC (power), M12 VCC (power), R2 VCCAUX (power)
part K pins: A1 GND (power), A16 GND (power), G7 GND (power), G8 GND (power), G9 GND (power), G10 GND (power), H7 GND (power), H8 GND (power), H9 GND (power), H10 GND (power), J7 GND (power), J8 GND (power), J9 GND (power), J10 GND (power), K7 GND (power), K8 GND (power), K9 GND (power), K10 GND (power), T1 GND (power), T16 GND (power)

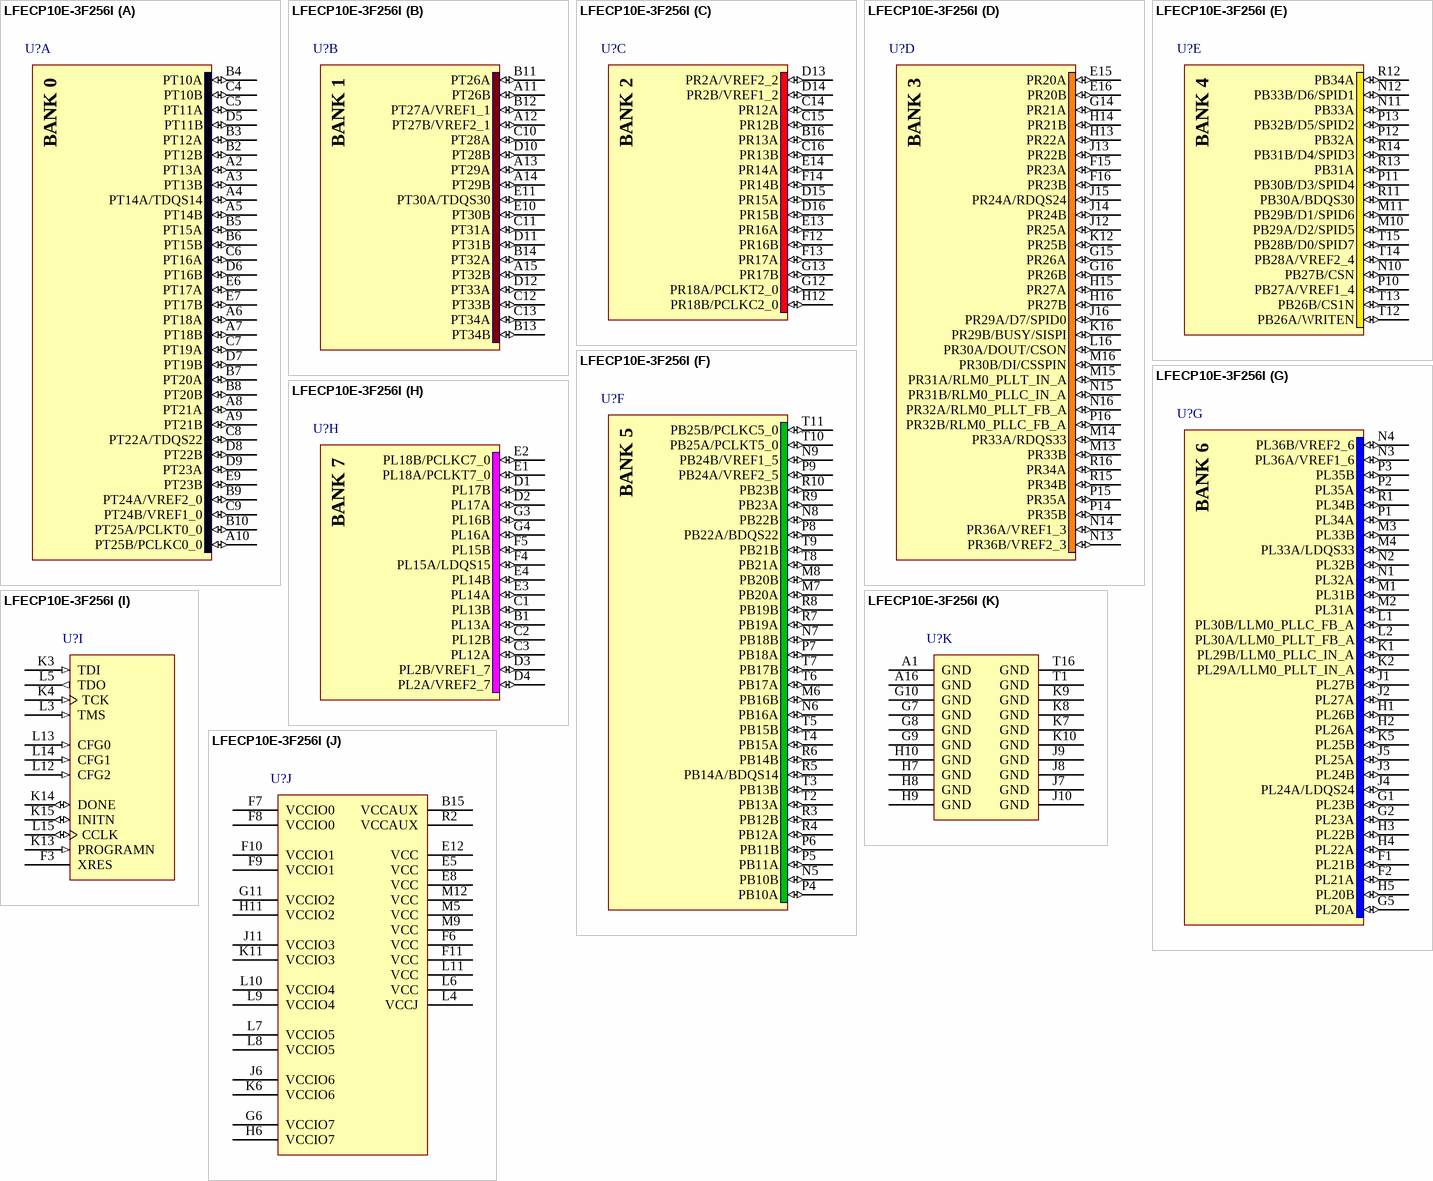
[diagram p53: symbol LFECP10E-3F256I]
